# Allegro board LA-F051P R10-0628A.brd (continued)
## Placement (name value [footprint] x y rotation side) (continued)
SW3  -  [SW_NTC311-EA1T-A160T_4P]  3.52 23.28 270 top
T1  -  [TPC12]  124.99 68.06 0 top
T2  -  [TPC12]  124.74 70.44 0 top
T7  -  [TPC12]  122.93 54.05 0 top
T8  -  [TPC12]  126.72 53.25 0 top
T9  -  [TPC12]  109.06 73.38 0 top
T10  -  [TPC12]  121 75.69 180 bottom
T11  -  [TPC12]  119.99 74.51 180 bottom
T12  -  [TPC12]  112.38 41.98 180 bottom
T13  -  [TPC12]  111.4 44.71 180 bottom
T14  -  [TPC12]  144.87 55.56 0 top
T15  -  [TPC12]  146.03 56.6 0 top
T16  -  [TPC12]  111.18 45.98 180 bottom
T17  -  [TPC12]  112.24 43.61 180 bottom
T18  -  [TPC12]  144.79 51.65 0 top
T19  -  [TPC12]  124.56 47.71 180 bottom
T21  -  [TPC12]  127.56 55.28 0 top
T113  -  [TPC12]  110.49 41.96 180 bottom
T114  -  [TPC12]  110.67 43.61 180 bottom
T115  -  [TPC12]  145.83 52.82 0 top
T116  -  [TPC12]  143.05 54.03 0 top
T121  -  [TPC12]  152.68 46.08 180 bottom
T122  -  [TPC12]  133.91 66.53 0 top
T123  -  [TPC12]  133.71 57.06 0 top
T124  -  [TPC12]  154.16 59.03 180 bottom
T125  -  [TPC12]  149.58 57.94 0 top
T126  -  [TPC12]  157.61 49.82 180 bottom
T127  -  [TPC12]  155.27 49.84 180 bottom
T128  -  [TPC12]  154.33 53.15 180 bottom
T129  -  [TPC12]  153.81 54.78 180 bottom
T130  -  [TPC12]  155.12 48.01 180 bottom
T183  -  [TPC12]  189.21 64.09 0 top
T184  -  [TPC12]  183.49 69.81 0 top
T185  -  [TPC12]  181.46 56.73 0 top
T187  -  [TPC12]  184 68.67 180 bottom
T189  -  [TPC12]  184.32 61.38 180 bottom
T192  -  [TPC12]  141.99 42.92 180 bottom
T193  -  [TPC12]  29.49 59.57 180 bottom
T194  -  [TPC12]  28.19 59.57 180 bottom
T195  -  [TPC12]  116.92 56.93 0 top
T196  -  [TPC12]  118.21 56.73 0 top
T197  -  [TPC12]  179.06 55.92 180 bottom
T198  -  [TPC12]  122.48 56.9 0 top
T199  -  [TPC12]  122.91 67.5 0 top
T200  -  [TPC12]  119.2 52.71 0 top
T201  -  [TPC12]  119.28 54.03 0 top
TC25  -  [TPC12]  22.53 67.52 0 top
TC29  -  [TPC12]  22.56 66.2 0 top
TC35  -  [TPC12]  27.89 67.45 180 bottom
TC36  -  [TPC12]  22.58 56.88 0 top
TC38  -  [TPC12]  22.53 58.19 0 top
TC39  -  [TPC12]  51.84 74.91 0 top
TC40  -  [TPC12]  50.7 75.62 0 top
TC41  -  [TPC12]  49.43 75.22 0 top
TC42  -  [TPC12]  48.08 75.75 0 top
TC43  -  [TPC12]  45.21 58.51 180 bottom
TC44  -  [TPC12]  25.5 60.18 180 bottom
TC45  -  [TPC12]  26.62 59.34 180 bottom
U15  -  [NPCT650JAAYX_QFN32_5X5]  183.33 46.69 0 top
U18  -  [W25Q256FVEIG_WSON8]  185.01 46.94 180 bottom
U48  -  [PCA9515BDGKR_VSSOP8]  202.33 25.22 0 top
U664  -  [TPS22966DPUR_SON14_2X3]  34.32 42.89 180 top
U683  -  [NL17SZ14DFT2G_SOT353-5]  186.92 39.33 90 bottom
U699  -  [MC74VHC1G32DFT2G_SC70-5]  25.5 53.81 180 top
U716  -  [TPS22966DPUR_SON14_2X3]  170.1 16.33 0 top
U717  -  [TPS22966DPUR_SON14_2X3]  180.88 33.5 180 top
U719  -  [TPS22966DPUR_SON14_2X3]  51.93 18.95 90 top
U720  -  [TPS22966DPUR_SON14_2X3]  35.73 41.48 0 top
U722  -  [TPS65982_BGA_96P]  26.01 64.47 270 top
U728  -  [G9091-330TO1U_TSOT-23-5]  64.97 80.16 270 top
U729  -  [MC74VHC1G09DFT2G_SC70-5]  204 79.29 270 bottom
UA2  -  [ALC3246-CG_MQFN48_6X6]  30.71 27.48 180 top
UC2  -  [74AUP1G07GW_TSSOP5]  104.63 46.2 270 bottom
UC7  -  [TC7SH08FU_SSOP5]  161.14 59.78 0 top
UC8  -  [TC7SH08FU_SSOP5]  204.05 58.03 180 top
UC9  -  [TC7SH08FU_SSOP5]  164.38 70.33 270 top
UC10  -  [TC7SH08FU_SSOP5]  191.3 59 90 bottom
UC11  -  [TC7SH08FU_SSOP5]  52.34 41.33 0 top
UC12  -  [74AHC1G09GW_TSSOP5]  143.38 77.71 90 bottom
UC13  -  [TC7SH08FU_SSOP5]  199.51 57.49 180 top
UCPU1  -  [SKL-U_BGA_1356P-T]  152.12 72.31 0 bottom
UD19  -  [H9CCNNN8JTMLAR-NTM_FBGA_178P]  99.62 23.5 90 top
UD20  -  [H9CCNNN8JTMLAR-NTM_FBGA_178P]  115.14 23.5 90 top
UD21  -  [H9CCNNN8JTMLAR-NTM_FBGA_178P]  133.2 23.5 90 top
UD22  -  [H9CCNNN8JTMLAR-NTM_FBGA_178P]  148.77 23.5 90 top
UE4  -  [MCP23017T-E-ML_QFN28_6X6]  30.96 15.58 90 bottom
UE5  -  [MEC5085-LZY_DQFN132_11X11]  188.06 59.52 90 top
US2  -  [G547I1P81U_MSOP8]  24.36 49.23 90 top
UT1  -  [AR-4C_BGA_337P-T]  37.74 55.69 270 top
UT5  -  [W25Q80DVZPIG_WSON8]  49.15 38.31 90 top
UT6  -  [W25Q64FVZPIG_WSON8_6X5]  20.42 40.44 0 top
UZ19  -  [TPS22961DNYR_WSON8]  166.17 65.78 90 top
UZ22  -  [TPS22961DNYR_WSON8]  164.81 46.84 90 top
UZ23  -  [TPS22961DNYR_WSON8]  49.07 48.65 90 top
UZ24  -  [SY6288C20AAC_SOT23-5]  201.91 40.98 90 top
UZ25  -  [TPS22961DNYR_WSON8]  157.2 74.38 90 top
UZ26  -  [TPS22961DNYR_WSON8]  57.12 75.73 0 top
YC1  -  [Y_X3G024000DC1H_4P]  155.56 72.63 270 top
YC2  -  [Y_9H03220008_2P]  152.88 44.28 180 top
YE1  -  [Y_Q13FC135000040_2P]  184.38 51.9 0 top
YT1  -  [Y_7V25000014_4P]  34.51 65.79 90 top

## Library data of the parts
C2-C7 C265 C352 C355 C375-C377 C397 C398 C401 C402 C612-C617 C621 C623 C713 C715 C720-C722 C963 C1060-C1069 C1102 C1145 C1158-C1164 C1166-C1169 C1199-C1201 C1203 C1204 C1208 C1211-C1218 C1220-C1223 C1225 C1226 C1229 C1254 C1256-C1258 C1264 C1273-C1275 C1278-C1280 C1289 C1292 C1293 C1297 C1298 C1301 C1302 C1304 C1309 C1321 C1322 C1324 C1325 C1341 C1346 C2973 C2983 C2984 CA3 CA4 CA7 CA23-CA25 CA27-CA35 CA40 CA42 CA53-CA56 CA68-CA72 CA78 CA80 CA87 CA97 CA100 CA103-CA106 CA111 CC4 CC5 CC8 CC10 CC21-CC29 CC32 CC33 CC174-CC179 CC194 CC195 CC199 CC202-CC206 CC209 CC211-CC214 CC217 CC218 CC220 CC223 CC224 CC240 CC248-CC253 CC264-CC270 CC282 CC283 CD1 CD3 CD5 CD7 CD29 CD33 CD37 CD39 CD41 CD43-CD47 CD51 CD53 CD57 CD59 CD61 CD63 CD85 CD87 CD89 CD91 CD117-CD120 CD129 CD132 CD133 CD135 CD136 CD139 CD140 CD142-CD146 CD148-CD181 CD183-CD187 CE3 CE10 CE13 CE14 CE17 CE21 CE22 CE38-CE41 CE43 CE46-CE68 CE72 CH11-CH14 CH95 CS44 CT43 CT44 CT53-CT56 CT95-CT98 CT144 CT151 CT152 CZ78 CZ82-CZ87 CZ89-CZ92 MC3 PC100-PC102 PC104-PC107 PC203-PC205 PC210-PC218 PC301 PC310 PC311 PC318 PC330-PC332 PC334-PC336 PC400-PC403 PC405 PC406 PC500 PC501 PC511 PC513 PC514 PC525 PC602-PC607 PC609 PC614 PC617 PC618 PC700-PC702 PC704 PC707 PC712 PC713 PC800 PC801 PC803 PC804 PC806 PC807 PC900 PC901 PC903 PC904 PC906 PC907 PC1004 PC1006 PC1014 PC1019-PC1022 PC1056 PC1064 PC1065 PC1067-PC1072 PC1074-PC1081 PC1083-PC1085 PC1087-PC1092 PC1094-PC1099 PC1103 PC1104 PC1106 PC1110-PC1113 PC1116-PC1118 PC1123 PC1124 PC1126-PC1128 PC1131-PC1134 PC1400 PC1408-PC1412 PC1417-PC1420 PC1535 PC1536 PC1538 = C_0402
C8 C94 C712 C716 C719 C962 C1143 C1205 C1339 C1347-C1350 C1353 C1985 C2982 CA74 CA82 CA83 CA86 CA107-CA110 CC31 CC34 CC35 CC279 CC280 CD2 CD4 CD6 CD8 CD30 CD34 CD38 CD42 CD58 CD60 CD62 CD64 CD86 CD88 CD90 CD92 CD147 CD182 CD196 CD197 CE4 CE42 CE45 CT9 CT88-CT90 CT164 CT165 PC103 PC200-PC202 PC206-PC209 PC247 PC309 PC312 PC314-PC317 PC319-PC329 PC333 PC337 PC404 PC407 PC502-PC510 PC512 PC515-PC524 PC526 PC527 PC600 PC601 PC608 PC610-PC613 PC615 PC616 PC703 PC1005 PC1007 PC1082 PC1086 PC1100-PC1102 PC1105 PC1107 PC1108 PC1114 PC1115 PC1119-PC1121 PC1125 PC1129 PC1130 PC1200-PC1246 PC1250-PC1252 PC1256-PC1258 PC1310-PC1321 PC1330-PC1334 PC1336 PC1337 PC1344-PC1354 PC1401-PC1406 PC1413-PC1416 = C_0603
C95-C98 C135 C618 C1345 C1354 C1984 CC95 CC125 CC181 CC182 CC185 CC186 CC225 CC256-CC261 CC281 CE70 CE71 CR24-CR26 CT1-CT8 CT17-CT26 CT29-CT42 CT47 CT50 CT52 CT57 CT62-CT68 CT71 CT72 CT74 CT80 CT81 CT83-CT86 CT91-CT94 CT99-CT103 CT107 CT108 CT149 CT150 CT153-CT163 CT166-CT179 PC1259-PC1305 PC1322-PC1328 PC1338-PC1343 = C_0201
C303 PC1306-PC1309 PC1329 = C_B2
CA2 CA5 CA6 CA98 CA99 CA101 CA102 CA112 CC210 CC271-CC274 PC108 PC302-PC307 PC313 PC528 PC529 PC705 PC706 PC708-PC711 PC802 PC805 PC902 PC905 PC1066 PC1093 PC1109 PC1122 = C_0805
CMOS1 JTAG1 RH442 RH443 = SHORTPADS: User Part Number: PART#
D72 D73 D94 = BAT54CW-7-F_SOT323-3
D75-D80 D82-D91 = ESD101-B1-02ELS_TSSLP-2-4-2
D81 DE11 DZ1-DZ3 = RB751S40T1G_SOD523-2
D122 PD102 = AZ5125-01HPR7G_SOD523-2
D123 = BZT52C15LP-7_DFN1006-2-2
DA1 DA2 = AZ5125-02SPR7G_SOT23-3
DA3 DA4 = PJDLC05C_SOT23-3
DA5 DA7 = ESD207-B1-02EL_TSLP-2-19-2
DI1 = IP4292CZ10-TBR_XSON10_2P5X1
DI2-DI4 = AZC199-02SPR7G_SOT23-3
DI7 = PESD24VS2UT_SOT23-3
FD1-FD4 = FIDUCIAL_C40M80
H1 H4 H7 H9 H12 H13 H18 H19 = H_2P0
H3 = H_1P8N
H6 H10 H11 H14-H17 = H_3P3
H20-H22 H24 H25 = EMIST_SUL-12A2M_1P
H23 = H_2P3X1P8N
H26 = H_3P2X0P8
JAPS1 = ACES_50506-01841-P01_18P
JBATT1 = FOX_GS73091-10272-7H_9P-T
JCAM JTS = CVILU_CI1806M2HRP-NH_6P
JDEG1 JLPDE1 = HB_A531015-SCHR21_10P
JEDP = ACES_50398-04041-001_40P
JFAN1 JSPK1 = ACES_50224-00401-001_4P
JHP1 = SINGA_2SJ3095-022111F_6P-T
JIO1 = JXT_FP270H-061G1AM_61P
JKB1 = E-T_6710K-Y15M-31L_15P
JNGFF1 = CONCR_213AAAA32FA_67P
JNGFF2 = CONCR_213MAAA32FA_67P-T
JP100 = ACES_88266-05001_5P
JPA1-JPA3 PJP14 PJP15 PJP300 PJP601 PJP800 PJP900 = JUMP_43X39
JRTC1 = ACES_50278-00201-001_2P
JSPI1 = ACES_50696-0200M-P01_20P
JTP1 = ACES_50506-00841-P01_8P
JUART = ACES_50207-00471-P01_4P-T
JUSB2 = TE_C-PT13-067_9P-T
JUSBC1 = JAE_DX07SA24XJ2_24P-T
JXDP1 = SAMTE_BSH-030-01-L-D-A_60P
L2-L5 = MURAT_BLM15PX181SN1D_2P
L55 ML9-ML11 = INPAQ_MCM1012B900F06BP_4P
LA2 LA4 = MURAT_BLM15PX600SN1D_2P
LA3 = MURAT_BLM21PG600SN1D_L0805_2P
LA6 LA7 = CHILI_PBY100505T-600Y-N_2P
LA14 = MURAT_BLM15BB220SN1D_2P
LED10-LED14 = LED_27-11-T1D-CP1Q1RY-3C_2P
LT1 = COILC_XFL4012-601MEC_2P
LT14 = CHILI_PBY160808T-300Y-N_2P
LT106 PL100 PL101 PL103 PL104 PL300 PL500 PL600 PL700 PL1004 = TAI-T_HCB2012KF-121T50_2P
MD9 MD10 = PESD5V0U2BT_SOT23-3
ML6 ML7 = MURAT_DLW21HN900SQ2L_4P
ML12 ML13 = MURAT_DLW21SN670HQ2L_4P
PC1073 PC1135 PC1537 = C_D
PD100 PD101 = TVNST52302AB0_SOT523-3
PD200 = BAT54CW_SOT323-3
PD201-PD206 PD300-PD302 = SDMK0340L-7-F_SOD323-2
PH1005-PH1009 PR100-PR106 PR201-PR230 PR232-PR235 PR237 PR239-PR275 PR277-PR291 PR301 PR305 PR307 PR310 PR312 PR316 PR317 PR320 PR322 PR323 PR325 PR327 PR400-PR413 PR502 PR504 PR506 PR508 PR509 PR511 PR600 PR601 PR603-PR605 PR608 PR610 PR611 PR700 PR701 PR704 PR705 PR707 PR708 PR800 PR802 PR804 PR805 PR901 PR902 PR904 PR905 PR1028 PR1058 PR1060-PR1065 PR1067-PR1075 PR1077-PR1079 PR1081 PR1084 PR1085 PR1087-PR1090 PR1092-PR1099 PR1107 PR1109 PR1112 PR1115 PR1118 PR1120-PR1124 PR1126-PR1128 PR1402 PR1404-PR1408 PR1412-PR1415 PR1417 PR1418 PR1422-PR1425 R7 R78-R81 R220 R249 R252 R287 R288 R290-R292 R535 R536 R540 R545 R884 R886 R910-R913 R916 R1006 R1027 R1103-R1105 R1140 R1141 R1161 R1162 R1175 R1176 R1178 R1179 R1186-R1188 R1191 R1216 R1255 R1299 R1376 R1377 R1443 R1446 R1454 R1460 R1462 R1468 R1472-R1478 R1873 R2662 RA15-RA20 RA24 RA25 RA27 RA28 RA35 RA37-RA39 RA41 RA48-RA51 RA57 RA58 RA60-RA62 RA75-RA77 RC1-RC7 RC9-RC18 RC20-RC23 RC25-RC27 RC29 RC44-RC50 RC52-RC67 RC69 RC71-RC75 RC77-RC96 RC109 RC110 RC112-RC115 RC120-RC124 RC126 RC128-RC141 RC152 RC153 RC157 RC158 RC161 RC163 RC165-RC168 RC175-RC178 RC183-RC191 RC215 RC217-RC220 RC224-RC227 RC229 RC230 RC236 RC237 RC239-RC243 RC245 RC246 RC272 RC277 RC280 RC283-RC285 RC288 RC291-RC293 RC312 RC313 RC319 RD17 RD19 RD21 RD22 RD25 RD26 RD35-RD38 RD45-RD48 RD51-RD118 RE2 RE3 RE6 RE7 RE13 RE14 RE22-RE27 RE31 RE33-RE36 RE52-RE61 RE63-RE86 RE89-RE103 RE121 RH24 RH56 RH58 RH59 RH127 RH129 RH139 RH144-RH153 RH438 RH440 RH441 RH456 RH461 RH556 RH557 RH562 RH563 RN19 RN20 RT1 RT2 RT5 RT10 RT46 RT113 RT190 RT199-RT201 RT242 RTCR1 RTCR2 RZ75 = R_0402
PJP500 PJP501 PJP600 PJP1002 = JUMP_43X118
PJP700 PJP1400 PJP1401 = JUMP_43X79
PL102 = MURAT_BLM15AG102SN1D_2P
PL301 = L_7X7X3_M_2P
PL501 = TAI-T_TMPC0518HP-1R5MG-D_2P
PL504 = CYNTE_PCMC063T-1R5MN_2P
PL601 = CYNTE_PCMB051B-1R0MS_2P
PL701 = L_5X5X3_M_2P
PL800 PL900 PL1400 PL1402 = TAI-T_HCB1608KF-121T3_L0603_2P
PL801 PL901 = TOKO_1239AS-H-2R2N-P2_2P
PL1005 = MAG_MMD05CZR47M_4P
PL1100-PL1102 = L_7X7X3_M
PL1401 PL1403 = TOKO_1277AS-H-1R0N-P2_2P
PQ100 = FDV301N_NL_SOT23-3
PQ101 QE9 = MMST3904-7-F_SOT323-3
PQ200-PQ203 PQ210-PQ212 = AON2405_DFN6-8
PQ204 PQ205 PQ213 PQ214 PQ221 PQ222 = NTR4502PT1G_SOT23-3
PQ206-PQ209 PQ215-PQ219 PQ223 PQ400 QA1 QA3 QC2 QE12-QE14 QH7-QH9 = DMN66D0LDW-7_SOT363-6
PQ220 PQ224 QA6 QA9 = SSM3K7002FU_SC70-3
PQ302 = L2N7002WT1G_SC70-3
PQ303 = SIR472DP-T1-GE3_POWERPAK8-5
PQ304 = SI7716ADN-T1-GE3_POWERPAK8-5
PQ305 = SI4483ADY-T1-GE3_SO8
PQ1302 = AON7934_DFN3X3A8-10
PR107 PR903 R2672 = R_0805
PR108 PR303 PR304 PR309 PR311 PR314 PR315 PR318 PR319 PR326 PR503 PR510 PR606 PR607 PR609 PR709 PR801 PR806 PR900 PR906 PR1024 PR1025 PR1027 PR1029 PR1059 PR1066 PR1076 PR1080 PR1083 PR1103 PR1110 PR1119 PR1125 PR1400 PR1401 PR1409 PR1411 PR1419-PR1421 R104 R250 R251 R289 R1200 R1210 R1212 R1436-R1442 R1444 R1445 R2663-R2665 RA26 RA30 RA31 RA54 RA59 RA63-RA65 RC19 RC154 RC155 RC169 RC171 RC213 RC221 RC228 RC247 RC248 RC290 RC296-RC298 RC301 RC310 RE32 RE62 RE104 RE105 RE107 RE120 RZ76 = R0402_0OHM
PR200 PR300 PR313 = R_1206_4P-D
PR306 PR321 PR501 PR507 PR1086 PR1101 PR1106 PR1114 = R_1206
PR308 PR324 PR500 PR505 PR602 PR612 PR702 PR703 PR803 PR1082 PR1091 PR1100 PR1102 PR1105 PR1111 PR1113 PR1116 PR1403 PR1416 R531 RA81 RA82 RC97 RT114 RT241 = R_0603
PR512 PR513 R1322 R1326 R1329 R1342 R1344 R1393 R2669 = R0805_0OHM
PRP100 RP5 RP6 RPE5 RPE7 = RP_0804_8P4R
PU200 = INA199A1DCKR_SC70-6
PU201 PU203 PU400 = LM393DMR2G_MICRO8
PU202 = RT9069-33GB_SOT23-5
PU300 = BQ24777ARUYR_WQFN28_4X4
PU401 PU402 = M74VHC1GT00DFT2G_SC70-5
PU500 = SY8286BRAC_QFN20_3X3
PU501 = SY8288CRAC_QFN20_3X3
PU600 = SY8210AQVC_QFN19_4X3
PU700 = SY8286RAC_QFN20_3X3
PU800 PU900 = TLV62150RGTR_QFN16_3X3
PU1000 = ISL95859AHRTZ-T_TQFN40_5X5
PU1100-PU1102 = AOZ5049QI_QFN24_5X3P5-S
PU1305 = ISL95808HRZ-TS2378_DFN8_2X2
PU1400 = TPS62134ARGT_QFN16_3X3
PU1401 = TPS62134BRGT_QFN16_3X3
Q40 Q41 Q71 QT19 = L2N7002WT1G_SC-70-3
Q70 = SI3457BDV-T1-E3_TSOP6
Q72 QZ9 = DMG2301U-7_SOT23-3
QE3 QE4 QE8 QE10 QE11 = MMBT3904WT1G_SC70-3
R9 R10 R60 R1403 R1405 R1457-R1459 R1461 R1463-R1465 R1471 RC51 RC316 RC317 RE87 RE88 RH126 RT3 RT4 RT6-RT9 RT11 RT12 RT15-RT18 RT21-RT23 RT25 RT26 RT33-RT40 RT43-RT45 RT47-RT52 RT119-RT121 RT164 RT187 RT188 RT243 = R_0201
R1125 R1318 R1320 R1323 R1325 R1327 R1333 R1335 R1343 R2670 R2671 RA80 RC143 RC170 RC211 RC214 RC216 RC299 RC304 RC309 RH357 = R0603_0OHM
RC172 RC318 = MURAT_BLM18EG221SN1D_2P
SW1 = SW_SSAL120100_3P
SW2 = SW_SKRBAAE010_4P
SW3 = SW_NTC311-EA1T-A160T_4P
T1 T2 T7-T19 T21 T113-T116 T121-T130 T183-T185 T187 T189 T192-T201 TC25 TC29 TC35 TC36 TC38-TC45 = TPC12
U15 = NPCT650JAAYX_QFN32_5X5
U18 = W25Q256FVEIG_WSON8
U48 = PCA9515BDGKR_VSSOP8
U664 U716 U717 U719 U720 = TPS22966DPUR_SON14_2X3
U683 = NL17SZ14DFT2G_SOT353-5
U699 = MC74VHC1G32DFT2G_SC70-5
U722 = TPS65982_BGA_96P
U728 = G9091-330TO1U_TSOT-23-5
U729 = MC74VHC1G09DFT2G_SC70-5
UA2 = ALC3246-CG_MQFN48_6X6
UC2 = 74AUP1G07GW_TSSOP5
UC7-UC11 UC13 = TC7SH08FU_SSOP5
UC12 = 74AHC1G09GW_TSSOP5
UCPU1 = SKL-U_BGA_1356P-T
UD19-UD22 = H9CCNNN8JTMLAR-NTM_FBGA_178P
UE4 = MCP23017T-E-ML_QFN28_6X6
UE5 = MEC5085-LZY_DQFN132_11X11
US2 = G547I1P81U_MSOP8
UT1 = AR-4C_BGA_337P-T
UT5 = W25Q80DVZPIG_WSON8
UT6 = W25Q64FVZPIG_WSON8_6X5
UZ19 UZ22 UZ23 UZ25 UZ26 = TPS22961DNYR_WSON8
UZ24 = SY6288C20AAC_SOT23-5
YC1 = Y_X3G024000DC1H_4P
YC2 = Y_9H03220008_2P
YE1 = Y_Q13FC135000040_2P
YT1 = Y_7V25000014_4P

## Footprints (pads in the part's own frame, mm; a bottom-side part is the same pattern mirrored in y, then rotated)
74AHC1G09GW_TSSOP5
  oval 0.381x1.346 smd: 1(0,0) 2(0.65,0) 3(1.3,0) 4(1.3,1.79) 5(0,1.79)
74AUP1G07GW_TSSOP5
  oval 0.381x1.346 smd: 1(0,0) 2(0.65,0) 3(1.3,0) 4(1.3,1.79) 5(0,1.79)
ACES_50207-00471-P01_4P-T
  oval 0.508x0.991 smd: 1(0,0) 2(-0.8,0) 3(-1.6,0) 4(-2.4,0)
  rect 1.194x1.702 smd: 5(-3.7,1.45) 6(1.3,1.45)
ACES_50224-00401-001_4P
  oval 0.61x1.549 smd: 1(0,0) 2(1,0) 3(2,0) 4(3,0)
  rect 1.194x1.803 smd: 5(4.3,-3.875) 6(-1.3,-3.875)
ACES_50278-00201-001_2P
  oval 0.787x1.905 smd: 1(0,0) 2(1.25,0)
  rect 1.295x3.353 smd: 3(-2.85,-4.925) 4(4.1,-4.925)
ACES_50398-04041-001_40P
  oval 0.254x1.295 smd: 1(0,0) 2(0.5,0) 3(1,0) 4(1.5,0) 5(2,0) 6(2.5,0) 7(3,0) 8(3.5,0) 9(4,0) 10(4.5,0) 11(5,0) 12(5.5,0) 13(6,0) 14(6.5,0) 15(7,0) 16(7.5,0) 17(8,0) 18(8.5,0) 19(9,0) 20(9.5,0) 21(10,0) 22(10.5,0) 23(11,0) 24(11.5,0) 25(12,0) 26(12.5,0) 27(13,0) 28(13.5,0) 29(14,0) 30(14.5,0) 31(15,0) 32(15.5,0) 33(16,0) 34(16.5,0) 35(17,0) 36(17.5,0) 37(18,0) 38(18.5,0) 39(19,0) 40(19.5,0)
  rect 1.194x3.2 smd: 41(-2.4,1.95) 45(21.9,1.95)
  rect 2.311x1.295 smd: 42(0.85,3.9) 43(9.75,3.9) 44(18.65,3.9)
ACES_50506-00841-P01_8P
  oval 0.305x0.889 smd: 1(0,0) 2(0.5,0) 3(1,0) 4(1.5,0) 5(2,0) 6(2.5,0) 7(3,0) 8(3.5,0)
  rect 0.991x2.007 smd: 9(-2.1,-3.05) 10(5.6,-3.05)
ACES_50506-01841-P01_18P
  oval 0.305x0.889 smd: 1(0,0) 2(0.5,0) 3(1,0) 4(1.5,0) 5(2,0) 6(2.5,0) 7(3,0) 8(3.5,0) 9(4,0) 10(4.5,0) 11(5,0) 12(5.5,0) 13(6,0) 14(6.5,0) 15(7,0) 16(7.5,0) 17(8,0) 18(8.5,0)
  rect 0.991x2.007 smd: 19(-2.1,-3.05) 20(10.6,-3.05)
ACES_50696-0200M-P01_20P
  oval 0.305x0.787 smd: 1(0,0) 2(-0.5,0) 3(-1,0) 4(-1.5,0) 5(-2,0) 6(-2.5,0) 7(-3,0) 8(-3.5,0) 9(-4,0) 10(-4.5,0) 11(-5,0) 12(-5.5,0) 13(-6,0) 14(-6.5,0) 15(-7,0) 16(-7.5,0) 17(-8,0) 18(-8.5,0) 19(-9,0) 20(-9.5,0)
  rect 0.406x0.787 smd: 21(1,-2.5) 22(-10.5,-2.5)
ACES_88266-05001_5P
  oval 0.787x2.007 smd: 1(0,0) 2(1.25,0) 3(2.5,0) 4(3.75,0) 5(5,0)
  rect 2.007x2.489 smd: 6(7.2,-4.05) 7(-2.2,-4.05)
ALC3246-CG_MQFN48_6X6
  oval 0.889x0.203 smd: 1(0,0) 2(0,-0.4) 3(0,-0.8) 4(0,-1.2) 5(0,-1.6) 6(0,-2) 7(0,-2.4) 8(0,-2.8) 9(0,-3.2) 10(0,-3.6) 11(0,-4) 12(0,-4.4) 25(6.1,-4.4) 26(6.1,-4) 27(6.1,-3.6) 28(6.1,-3.2) 29(6.1,-2.8) 30(6.1,-2.4) 31(6.1,-2) 32(6.1,-1.6) 33(6.1,-1.2) 34(6.1,-0.8) 35(6.1,-0.4) 36(6.1,0)
  oval 0.203x0.889 smd: 13(0.85,-5.25) 14(1.25,-5.25) 15(1.65,-5.25) 16(2.05,-5.25) 17(2.45,-5.25) 18(2.85,-5.25) 19(3.25,-5.25) 20(3.65,-5.25) 21(4.05,-5.25) 22(4.45,-5.25) 23(4.85,-5.25) 24(5.25,-5.25) 37(5.25,0.85) 38(4.85,0.85) 39(4.45,0.85) 40(4.05,0.85) 41(3.65,0.85) 42(3.25,0.85) 43(2.85,0.85) 44(2.45,0.85) 45(2.05,0.85) 46(1.65,0.85) 47(1.25,0.85) 48(0.85,0.85)
  rect 4.394x4.394 smd: 49(3.05,-2.2)
AON2405_DFN6-8
  oval 0.305x0.33 smd: 1(0,0) 2(0.65,0) 3(1.3,0) 4(1.3,1.725) 5(0.65,1.725) 6(0,1.725)
  rect 0.94x0.991 smd: 7(0.325,0.863)
  rect 0.229x0.813 smd: 8(1.315,0.902)
AON7934_DFN3X3A8-10
  oval 0.457x0.508 smd: 1(0,0) 2(0.65,0) 3(1.3,0) 4(1.95,0) 5(1.95,2.76) 6(1.3,2.76) 7(0.65,2.76) 8(0,2.76)
  rect 2.54x1.041 smd: 9(0.975,1.813)
  rect 2.54x0.559 smd: 10(0.975,0.708)
AOZ5049QI_QFN24_5X3P5-S
  oval 0.254x0.762 smd: 1(0,0) 2(0.5,0) 3(1,0) 4(1.5,0) 5(2,0)
  rect 3.15x1.473 smd: 6(1.47,1.31)
  custom 0.588x0.588 smd: 7(1,2.425)
  rect 1.956x0.864 smd: 8(1.25,4.787)
  oval 0.762x0.254 smd: 9(-0.675,2.925) 10(-0.675,2.425) 11(-0.675,1.925) 12(-0.675,1.425) 13(-0.675,0.925) 14(-0.675,0.425)
AR-4C_BGA_337P-T
  round 0.254 smd: A1(0,0) A23(-10.12,0) AA2(-0.46,9.2) AA22(-9.66,9.2) AB2(-0.46,9.66) AB3(-0.92,9.66) AB4(-1.38,9.66) AB5(-1.84,9.66) AB6(-2.3,9.66) AB7(-2.76,9.66) AB8(-3.22,9.66) AB9(-3.68,9.66) AB10(-4.14,9.66) AB11(-4.6,9.66) AB12(-5.06,9.66) AB13(-5.52,9.66) AB14(-5.98,9.66) AB15(-6.44,9.66) AB16(-6.9,9.66) AB17(-7.36,9.66) AB18(-7.82,9.66) AB19(-8.28,9.66) AB20(-8.74,9.66) AB21(-9.2,9.66) AB22(-9.66,9.66) AC1(0,10.12) AC23(-10.12,10.12) B2(-0.46,0.46) B3(-0.92,0.46) B4(-1.38,0.46) B5(-1.84,0.46) B6(-2.3,0.46) B7(-2.76,0.46) B8(-3.22,0.46) B9(-3.68,0.46) B10(-4.14,0.46) B11(-4.6,0.46) B12(-5.06,0.46) B13(-5.52,0.46) B14(-5.98,0.46) B15(-6.44,0.46) B16(-6.9,0.46) B17(-7.36,0.46) B18(-7.82,0.46) B19(-8.28,0.46) B20(-8.74,0.46) B21(-9.2,0.46) B22(-9.66,0.46) C2(-0.46,0.92) C22(-9.66,0.92) D2(-0.46,1.38) D4(-1.16,1.16) D5(-1.81,1.16) D6(-2.46,1.16) D8(-3.11,1.16) D9(-3.76,1.16) D11(-4.41,1.16) D12(-5.06,1.16) D13(-5.71,1.16) D15(-6.36,1.16) D16(-7.01,1.16) D18(-7.66,1.16) D19(-8.31,1.16) D20(-8.96,1.16) D22(-9.66,1.38) E2(-0.46,1.84) E4(-1.16,1.81) E5(-1.81,1.81) E6(-2.46,1.81) E8(-3.11,1.81) E9(-3.76,1.81) E11(-4.41,1.81) E12(-5.06,1.81) E13(-5.71,1.81) E15(-6.36,1.81) E16(-7.01,1.81) E18(-7.66,1.81) E19(-8.31,1.81) E20(-8.96,1.81) E22(-9.66,1.84) F2(-0.46,2.3) F4(-1.16,2.46) F5(-1.81,2.46) F6(-2.46,2.46) F8(-3.11,2.46) F9(-3.76,2.46) F11(-4.41,2.46) F12(-5.06,2.46) F13(-5.71,2.46) F15(-6.36,2.46) F16(-7.01,2.46) F18(-7.66,2.46) F19(-8.31,2.46) F20(-8.96,2.46) F22(-9.66,2.3) G2(-0.46,2.76) G22(-9.66,2.76) H2(-0.46,3.22) H4(-1.16,3.11) H5(-1.81,3.11) H6(-2.46,3.11) H8(-3.11,3.11) H9(-3.76,3.11) H11(-4.41,3.11) H12(-5.06,3.11) H13(-5.71,3.11) H15(-6.36,3.11) H16(-7.01,3.11) H18(-7.66,3.11) H19(-8.31,3.11) H20(-8.96,3.11) H22(-9.66,3.22) J2(-0.46,3.68) J4(-1.16,3.76) J5(-1.81,3.76) J6(-2.46,3.76) J8(-3.11,3.76) J9(-3.76,3.76) J11(-4.41,3.76) J12(-5.06,3.76) J13(-5.71,3.76) J15(-6.36,3.76) J16(-7.01,3.76) J18(-7.66,3.76) J19(-8.31,3.76) J20(-8.96,3.76) J22(-9.66,3.68) K2(-0.46,4.14) K22(-9.66,4.14) L2(-0.46,4.6) L4(-1.16,4.41) L5(-1.81,4.41) L6(-2.46,4.41) L8(-3.11,4.41) L9(-3.76,4.41) L11(-4.41,4.41) L12(-5.06,4.41) L13(-5.71,4.41) L15(-6.36,4.41) L16(-7.01,4.41) L18(-7.66,4.41) L19(-8.31,4.41) L20(-8.96,4.41) L22(-9.66,4.6) M2(-0.46,5.06) M4(-1.16,5.06) M5(-1.81,5.06) M6(-2.46,5.06) M8(-3.11,5.06) M9(-3.76,5.06) M11(-4.41,5.06) M12(-5.06,5.06) M13(-5.71,5.06) M15(-6.36,5.06) M16(-7.01,5.06) M18(-7.66,5.06) M19(-8.31,5.06) M20(-8.96,5.06) M22(-9.66,5.06) N2(-0.46,5.52) N4(-1.16,5.71) N5(-1.81,5.71) N6(-2.46,5.71) N8(-3.11,5.71) N9(-3.76,5.71) N11(-4.41,5.71) N12(-5.06,5.71) N13(-5.71,5.71) N15(-6.36,5.71) N16(-7.01,5.71) N18(-7.66,5.71) N19(-8.31,5.71) N20(-8.96,5.71) N22(-9.66,5.52) P2(-0.46,5.98) P22(-9.66,5.98) R2(-0.46,6.44) R4(-1.16,6.36) R5(-1.81,6.36) R6(-2.46,6.36) R8(-3.11,6.36) R9(-3.76,6.36) R11(-4.41,6.36) R12(-5.06,6.36) R13(-5.71,6.36) R15(-6.36,6.36) R16(-7.01,6.36) R18(-7.66,6.36) R19(-8.31,6.36) R20(-8.96,6.36) R22(-9.66,6.44) T2(-0.46,6.9) T4(-1.16,7.01) T5(-1.81,7.01) T6(-2.46,7.01) T8(-3.11,7.01) T9(-3.76,7.01) T11(-4.41,7.01) T12(-5.06,7.01) T13(-5.71,7.01) T15(-6.36,7.01) T16(-7.01,7.01) T18(-7.66,7.01) T19(-8.31,7.01) T20(-8.96,7.01) T22(-9.66,6.9) U2(-0.46,7.36) U22(-9.66,7.36) V2(-0.46,7.82) V4(-1.16,7.66) V5(-1.81,7.66) V6(-2.46,7.66) V8(-3.11,7.66) V9(-3.76,7.66) V11(-4.41,7.66) V12(-5.06,7.66) V13(-5.71,7.66) V15(-6.36,7.66) V16(-7.01,7.66) V18(-7.66,7.66) V19(-8.31,7.66) V20(-8.96,7.66) V22(-9.66,7.82) W2(-0.46,8.28) W4(-1.16,8.31) W5(-1.81,8.31) W6(-2.46,8.31) W8(-3.11,8.31) W9(-3.76,8.31) W11(-4.41,8.31) W12(-5.06,8.31) W13(-5.71,8.31) W15(-6.36,8.31) W16(-7.01,8.31) W18(-7.66,8.31) W19(-8.31,8.31) W20(-8.96,8.31) W22(-9.66,8.28) Y2(-0.46,8.74) Y4(-1.16,8.96) Y5(-1.81,8.96) Y6(-2.46,8.96) Y8(-3.11,8.96) Y9(-3.76,8.96) Y11(-4.41,8.96) Y12(-5.06,8.96) Y13(-5.71,8.96) Y15(-6.36,8.96) Y16(-7.01,8.96) Y18(-7.66,8.96) Y19(-8.31,8.96) Y20(-8.96,8.96) Y22(-9.66,8.74)
  oval 0.178x0.33 smd: A2(-0.46,0) A3(-0.92,0) A4(-1.38,0) A5(-1.84,0) A6(-2.3,0) A7(-2.76,0) A8(-3.22,0) A9(-3.68,0) A10(-4.14,0) A11(-4.6,0) A12(-5.06,0) A13(-5.52,0) A14(-5.98,0) A15(-6.44,0) A16(-6.9,0) A17(-7.36,0) A18(-7.82,0) A19(-8.28,0) A20(-8.74,0) A21(-9.2,0) A22(-9.66,0) AC2(-0.46,10.12) AC3(-0.92,10.12) AC4(-1.38,10.12) AC5(-1.84,10.12) AC6(-2.3,10.12) AC7(-2.76,10.12) AC8(-3.22,10.12) AC9(-3.68,10.12) AC10(-4.14,10.12) AC11(-4.6,10.12) AC12(-5.06,10.12) AC13(-5.52,10.12) AC14(-5.98,10.12) AC15(-6.44,10.12) AC16(-6.9,10.12) AC17(-7.36,10.12) AC18(-7.82,10.12) AC19(-8.28,10.12) AC20(-8.74,10.12) AC21(-9.2,10.12) AC22(-9.66,10.12)
  oval 0.33x0.178 smd: AA1(0,9.2) AA23(-10.12,9.2) AB1(0,9.66) AB23(-10.12,9.66) B1(0,0.46) B23(-10.12,0.46) C1(0,0.92) C23(-10.12,0.92) D1(0,1.38) D23(-10.12,1.38) E1(0,1.84) E23(-10.12,1.84) F1(0,2.3) F23(-10.12,2.3) G1(0,2.76) G23(-10.12,2.76) H1(0,3.22) H23(-10.12,3.22) J1(0,3.68) J23(-10.12,3.68) K1(0,4.14) K23(-10.12,4.14) L1(0,4.6) L23(-10.12,4.6) M1(0,5.06) M23(-10.12,5.06) N1(0,5.52) N23(-10.12,5.52) P1(0,5.98) P23(-10.12,5.98) R1(0,6.44) R23(-10.12,6.44) T1(0,6.9) T23(-10.12,6.9) U1(0,7.36) U23(-10.12,7.36) V1(0,7.82) V23(-10.12,7.82) W1(0,8.28) W23(-10.12,8.28) Y1(0,8.74) Y23(-10.12,8.74)
AZ5125-01HPR7G_SOD523-2
  rect 0.61x0.787 smd: 1(0,0) 2(1.5,0)
AZ5125-02SPR7G_SOT23-3
  oval 1.016x1.524 smd: 1(0,0) 2(0.965,2.083) 3(-0.965,2.083)
AZC199-02SPR7G_SOT23-3
  oval 1.016x1.524 smd: 1(0,0) 2(0.965,2.083) 3(-0.965,2.083)
BAT54CW-7-F_SOT323-3
  oval 0.711x0.889 smd: 1(0,0) 2(-0.65,-1.9) 3(0.65,-1.9)
BAT54CW_SOT323-3
  oval 0.711x0.889 smd: 1(0,0) 2(-0.65,-1.9) 3(0.65,-1.9)
BQ24777ARUYR_WQFN28_4X4
  oval 0.889x0.203 smd: 1(0,0) 2(0,-0.4) 3(0,-0.8) 4(0,-1.2) 5(0,-1.6) 6(0,-2) 7(0,-2.4) 15(4.1,-2.4) 16(4.1,-2) 17(4.1,-1.6) 18(4.1,-1.2) 19(4.1,-0.8) 20(4.1,-0.4) 21(4.1,0)
  oval 0.203x0.889 smd: 8(0.85,-3.25) 9(1.25,-3.25) 10(1.65,-3.25) 11(2.05,-3.25) 12(2.45,-3.25) 13(2.85,-3.25) 14(3.25,-3.25) 22(3.25,0.85) 23(2.85,0.85) 24(2.45,0.85) 25(2.05,0.85) 26(1.65,0.85) 27(1.25,0.85) 28(0.85,0.85)
  rect 2.591x2.591 smd: 29(2.05,-1.2)
BZT52C15LP-7_DFN1006-2-2
  rect 0.406x0.711 smd: 1(0,0) 2(0.7,0)
C_0201
  rect 0.381x0.356 smd: 1(0,0) 2(0.584,0)
C_0402
  rect 0.508x0.559 smd: 1(0,0) 2(0.914,0)
C_0603
  rect 0.635x0.889 smd: 1(0,0) 2(1.397,0)
C_0805
  rect 0.813x1.397 smd: 1(0,0) 2(1.702,0)
C_B2
  rect 1.346x2.692 smd: 1(0,0) 2(-2.75,0)
C_D
  rect 2.388x2.896 smd: 1(0,0) 2(6.1,0)
CHILI_PBY100505T-600Y-N_2P
  rect 0.457x0.508 smd: 1(0,0) 2(0.85,0)
CHILI_PBY160808T-300Y-N_2P
  rect 0.559x1.041 smd: 1(0,0) 2(1.3,0)
COILC_XFL4012-601MEC_2P
  rect 0.991x3.404 smd: 1(0,0) 2(2.37,0)
CONCR_213AAAA32FA_67P
  round 1.092 hole 1.092 unplated: (-0.75,-5.275)
  round 1.6 hole 1.6 unplated: (19.25,-5.275)
  oval 0.305x1.549 smd: 1(0,0) 2(0.25,-7.55) 3(0.5,0) 4(0.75,-7.55) 5(1,0) 6(1.25,-7.55) 7(1.5,0) 8(3.75,-7.55) 9(4,0) 10(4.25,-7.55) 11(4.5,0) 12(4.75,-7.55) 13(5,0) 14(5.25,-7.55) 15(5.5,0) 16(5.75,-7.55) 17(6,0) 18(6.25,-7.55) 19(6.5,0) 20(6.75,-7.55) 21(7,0) 22(7.25,-7.55) 23(7.5,0) 24(7.75,-7.55) 25(8,0) 26(8.25,-7.55) 27(8.5,0) 28(8.75,-7.55) 29(9,0) 30(9.25,-7.55) 31(9.5,0) 32(9.75,-7.55) 33(10,0) 34(10.25,-7.55) 35(10.5,0) 36(10.75,-7.55) 37(11,0) 38(11.25,-7.55) 39(11.5,0) 40(11.75,-7.55) 41(12,0) 42(12.25,-7.55) 43(12.5,0) 44(12.75,-7.55) 45(13,0) 46(13.25,-7.55) 47(13.5,0) 48(13.75,-7.55) 49(14,0) 50(14.25,-7.55) 51(14.5,0) 52(14.75,-7.55) 53(15,0) 54(15.25,-7.55) 55(15.5,0) 56(15.75,-7.55) 57(16,0) 58(16.25,-7.55) 59(16.5,0) 60(16.75,-7.55) 61(17,0) 62(17.25,-7.55) 63(17.5,0) 64(17.75,-7.55) 65(18,0) 66(18.25,-7.55) 67(18.5,0)
  rect 1.194x2.743 smd: 68(-1.1,-0.775) 69(19.6,-0.775)
CONCR_213MAAA32FA_67P-T
  round 1.092 hole 1.092 unplated: (-0.75,-5.275)
  round 1.6 hole 1.6 unplated: (19.25,-5.275)
  oval 0.305x1.549 smd: 1(0,0) 2(0.25,-7.55) 3(0.5,0) 4(0.75,-7.55) 5(1,0) 6(1.25,-7.55) 7(1.5,0) 8(1.75,-7.55) 9(2,0) 10(2.25,-7.55) 11(2.5,0) 12(2.75,-7.55) 13(3,0) 14(3.25,-7.55) 15(3.5,0) 16(3.75,-7.55) 17(4,0) 18(4.25,-7.55) 19(4.5,0) 20(4.75,-7.55) 21(5,0) 22(5.25,-7.55) 23(5.5,0) 24(5.75,-7.55) 25(6,0) 26(6.25,-7.55) 27(6.5,0) 28(6.75,-7.55) 29(7,0) 30(7.25,-7.55) 31(7.5,0) 32(7.75,-7.55) 33(8,0) 34(8.25,-7.55) 35(8.5,0) 36(8.75,-7.55) 37(9,0) 38(9.25,-7.55) 39(9.5,0) 40(9.75,-7.55) 41(10,0) 42(10.25,-7.55) 43(10.5,0) 44(10.75,-7.55) 45(11,0) 46(11.25,-7.55) 47(11.5,0) 48(11.75,-7.55) 49(12,0) 50(12.25,-7.55) 51(12.5,0) 52(12.75,-7.55) 53(13,0) 54(13.25,-7.55) 55(13.5,0) 56(13.75,-7.55) 57(14,0) 58(14.25,-7.55) 59(16.5,0) 60(16.75,-7.55) 61(17,0) 62(17.25,-7.55) 63(17.5,0) 64(17.75,-7.55) 65(18,0) 66(18.25,-7.55) 67(18.5,0)
  rect 1.194x2.743 smd: 68(-1.1,-0.775) 69(19.6,-0.775)
CVILU_CI1806M2HRP-NH_6P
  oval 0.508x0.991 smd: 1(0,0) 2(0.8,0) 3(1.6,0) 4(2.4,0) 5(3.2,0) 6(4,0)
  rect 1.194x1.702 smd: 7(5.3,-1.95) 8(-1.3,-1.95)
CYNTE_PCMB051B-1R0MS_2P
  rect 2.159x2.794 smd: 1(0,0) 2(4.35,0)
CYNTE_PCMC063T-1R5MN_2P
  rect 2.159x3.505 smd: 1(0,0) 2(5.85,0)
DMG2301U-7_SOT23-3
  oval 1.016x1.524 smd: 1(0,0) 2(0.965,2.083) 3(-0.965,2.083)
DMN66D0LDW-7_SOT363-6
  oval 0.432x0.61 smd: 1(0,0) 2(0.65,0) 3(1.3,0) 4(1.3,1.9) 5(0.65,1.9) 6(0,1.9)
E-T_6710K-Y15M-31L_15P
  oval 0.305x0.965 smd: 1(0,0) 2(0.5,0) 3(1,0) 4(1.5,0) 5(2,0) 6(2.5,0) 7(3,0) 8(3.5,0) 9(4,0) 10(4.5,0) 11(5,0) 12(5.5,0) 13(6,0) 14(6.5,0) 15(7,0)
  rect 0.305x1.143 smd: 16(7.885,-2.965) 17(-0.885,-2.965)
EMIST_SUL-12A2M_1P
  rect 6.909x1.194 smd: 1(0,0)
ESD101-B1-02ELS_TSSLP-2-4-2
  rect 0.279x0.381 smd: 1(0,0) 2(0.38,0)
ESD207-B1-02EL_TSLP-2-19-2
  rect 0.356x0.61 smd: 1(0,0) 2(0.65,0)
FDV301N_NL_SOT23-3
  oval 1.016x1.524 smd: 1(0,0) 2(0.965,2.083) 3(-0.965,2.083)
FIDUCIAL_C40M80
  round 1.016 smd: 1(0,0)
FOX_GS73091-10272-7H_9P-T
  rect 0.66x5.004 smd: 1(0,0) 2(-1.5,0) 3(-3,0) 4(-4.5,0) 5(-6,0) 6(-7.5,0) 7(-9,0) 8(-10.5,0) 9(-12,0)
  rect 2.489x2.997 smd: 10(-14.5,4.45) 11(2.5,4.45)
G547I1P81U_MSOP8
  oval 0.381x1.549 smd: 1(0,0) 2(0.65,0) 3(1.3,0) 4(1.95,0) 5(1.95,4.37) 6(1.3,4.37) 7(0.65,4.37) 8(0,4.37)
G9091-330TO1U_TSOT-23-5
  oval 0.508x0.965 smd: 1(0,0) 2(0.95,0) 3(1.9,0) 4(1.9,2.35) 5(0,2.35)
H9CCNNN8JTMLAR-NTM_FBGA_178P
  round 0.343 smd: A1(0,0) A2(0.8,0) A3(1.6,0) A4(2.4,0) A5(3.2,0) A6(4,0) A8(5.601,0) A9(6.401,0) A10(7.201,0) A11(8.001,0) A12(8.801,0) A13(9.601,0) B1(0,-0.65) B2(0.8,-0.65) B3(1.6,-0.65) B4(2.4,-0.65) B5(3.2,-0.65) B6(4,-0.65) B8(5.601,-0.65) B9(6.401,-0.65) B10(7.201,-0.65) B11(8.001,-0.65) B12(8.801,-0.65) B13(9.601,-0.65) C2(0.8,-1.3) C3(1.6,-1.3) C4(2.4,-1.3) C5(3.2,-1.3) C6(4,-1.3) C8(5.601,-1.3) C9(6.401,-1.3) C10(7.201,-1.3) C11(8.001,-1.3) C12(8.801,-1.3) D2(0.8,-1.95) D3(1.6,-1.95) D4(2.4,-1.95) D5(3.2,-1.95) D6(4,-1.95) D8(5.601,-1.95) D9(6.401,-1.95) D10(7.201,-1.95) D11(8.001,-1.95) D12(8.801,-1.95) E2(0.8,-2.6) E3(1.6,-2.6) E4(2.4,-2.6) E5(3.2,-2.6) E6(4,-2.6) E8(5.601,-2.6) E9(6.401,-2.6) E10(7.201,-2.6) E11(8.001,-2.6) E12(8.801,-2.6) F2(0.8,-3.25) F3(1.6,-3.25) F4(2.4,-3.25) F5(3.2,-3.25) F6(4,-3.25) F8(5.601,-3.25) F9(6.401,-3.25) F10(7.201,-3.25) F11(8.001,-3.25) F12(8.801,-3.25) G2(0.8,-3.9) G3(1.6,-3.9) G4(2.4,-3.9) G5(3.2,-3.9) G6(4,-3.9) G8(5.601,-3.9) G9(6.401,-3.9) G10(7.201,-3.9) G11(8.001,-3.9) G12(8.801,-3.9) H2(0.8,-4.55) H3(1.6,-4.55) H4(2.4,-4.55) H5(3.2,-4.55) H6(4,-4.55) H8(5.601,-4.55) H9(6.401,-4.55) H10(7.201,-4.55) H11(8.001,-4.55) H12(8.801,-4.55) J2(0.8,-5.2) J3(1.6,-5.2) J4(2.4,-5.2) J5(3.2,-5.2) J6(4,-5.2) J8(5.601,-5.2) J9(6.401,-5.2) J10(7.201,-5.2) J11(8.001,-5.2) J12(8.801,-5.2) K2(0.8,-5.85) K3(1.6,-5.85) K4(2.4,-5.85) K5(3.2,-5.85) K6(4,-5.85) K8(5.601,-5.85) K9(6.401,-5.85) K10(7.201,-5.85) K11(8.001,-5.85) K12(8.801,-5.85) L2(0.8,-6.5) L3(1.6,-6.5) L4(2.4,-6.5) L5(3.2,-6.5) L6(4,-6.5) L8(5.601,-6.5) L9(6.401,-6.5) L10(7.201,-6.5) L11(8.001,-6.5) L12(8.801,-6.5) M2(0.8,-7.15) M3(1.6,-7.15) M4(2.4,-7.15) M5(3.2,-7.15) M6(4,-7.15) M8(5.601,-7.15) M9(6.401,-7.15) M10(7.201,-7.15) M11(8.001,-7.15) M12(8.801,-7.15) N2(0.8,-7.8) N3(1.6,-7.8) N4(2.4,-7.8) N5(3.2,-7.8) N6(4,-7.8) N8(5.601,-7.8) N9(6.401,-7.8) N10(7.201,-7.8) N11(8.001,-7.8) N12(8.801,-7.8) P2(0.8,-8.45) P3(1.6,-8.45) P4(2.4,-8.45) P5(3.2,-8.45) P6(4,-8.45) P8(5.601,-8.45) P9(6.401,-8.45) P10(7.201,-8.45) P11(8.001,-8.45) P12(8.801,-8.45) R2(0.8,-9.1) R3(1.6,-9.1) R4(2.4,-9.1) R5(3.2,-9.1) R6(4,-9.1) R8(5.601,-9.1) R9(6.401,-9.1) R10(7.201,-9.1) R11(8.001,-9.1) R12(8.801,-9.1) T1(0,-9.75) T2(0.8,-9.75) T3(1.6,-9.75) T4(2.4,-9.75) T5(3.2,-9.75) T6(4,-9.75) T8(5.601,-9.75) T9(6.401,-9.75) T10(7.201,-9.75) T11(8.001,-9.75) T12(8.801,-9.75) T13(9.601,-9.75) U1(0,-10.4) U2(0.8,-10.4) U3(1.6,-10.4) U4(2.4,-10.4) U5(3.2,-10.4) U6(4,-10.4) U8(5.601,-10.4) U9(6.401,-10.4) U10(7.201,-10.4) U11(8.001,-10.4) U12(8.801,-10.4) U13(9.601,-10.4)
H_1P8N
  round 1.803 hole 1.803 unplated: (0,0)
H_2P0
  round 2.515 hole 2.007: 1(0,0)
H_2P3X1P8N
  oval 2.311x1.803 hole 2.311x1.803 unplated: (0,0)
H_3P2X0P8
  oval 3.708x1.295 hole 3.2x0.787: 1(0,0)
H_3P3
  round 3.81 hole 3.302: 1(0,0)
HB_A531015-SCHR21_10P
  oval 0.305x0.889 smd: 1(0,0) 2(0.5,0) 3(1,0) 4(1.5,0) 5(2,0) 6(2.5,0) 7(3,0) 8(3.5,0) 9(4,0) 10(4.5,0)
  rect 0.991x2.007 smd: 11(6.6,-3.05) 12(-2.1,-3.05)
INA199A1DCKR_SC70-6
  oval 0.406x0.889 smd: 1(0,0) 2(0.65,0) 3(1.3,0) 4(1.3,2.2) 5(0.65,2.2) 6(0,2.2)
INPAQ_MCM1012B900F06BP_4P
  rect 0.711x0.305 smd: 1(0,0) 2(1.25,0) 3(1.25,-0.5) 4(0,-0.5)
IP4292CZ10-TBR_XSON10_2P5X1
  oval 0.254x0.889 smd: 1(0,0)
  oval 0.254x0.838 smd: 2(0.5,-0.025) 3(1,-0.025) 4(1.5,-0.025) 5(2,-0.025) 6(2,1.125) 7(1.5,1.125) 8(1,1.125) 9(0.5,1.125) 10(0,1.125)
ISL95808HRZ-TS2378_DFN8_2X2
  oval 0.254x0.787 smd: 1(0,0) 2(0.5,0) 3(1,0) 4(1.5,0) 5(1.5,2.2) 6(1,2.2) 7(0.5,2.2) 8(0,2.2)
  rect 1.549x0.889 smd: 9(0.75,1.1)
ISL95859AHRTZ-T_TQFN40_5X5
  oval 0.889x0.203 smd: 1(0,0) 2(0,-0.4) 3(0,-0.8) 4(0,-1.2) 5(0,-1.6) 6(0,-2) 7(0,-2.4) 8(0,-2.8) 9(0,-3.2) 10(0,-3.6) 21(5.1,-3.6) 22(5.1,-3.2) 23(5.1,-2.8) 24(5.1,-2.4) 25(5.1,-2) 26(5.1,-1.6) 27(5.1,-1.2) 28(5.1,-0.8) 29(5.1,-0.4) 30(5.1,0)
  oval 0.203x0.889 smd: 11(0.75,-4.35) 12(1.15,-4.35) 13(1.55,-4.35) 14(1.95,-4.35) 15(2.35,-4.35) 16(2.75,-4.35) 17(3.15,-4.35) 18(3.55,-4.35) 19(3.95,-4.35) 20(4.35,-4.35) 31(4.35,0.75) 32(3.95,0.75) 33(3.55,0.75) 34(3.15,0.75) 35(2.75,0.75) 36(2.35,0.75) 37(1.95,0.75) 38(1.55,0.75) 39(1.15,0.75) 40(0.75,0.75)
  rect 3.505x3.505 smd: 41(2.55,-1.8)
JAE_DX07SA24XJ2_24P-T
  round 0.762 hole 0.762 unplated: (-0.85,-0.66)
  oval 0.94x0.762 hole 0.94x0.762 unplated: (6.35,-0.66)
  custom 0.275x0.275 hole 0.61x1.6: 1(-1.85,-5.06) 4(7.35,-5.06)
  oval 1.092x2.108 hole 0.61x1.6: 2(-1.85,-2.06) 3(7.35,-2.06)
  rect 1.499x1.6 smd: 7(0.75,-5.91) 8(4.75,-5.91)
  oval 0.305x1.092 smd: A1(0,0) A2(0.5,0) A3(1,0) A4(1.5,0) A5(2,0) A6(2.5,0) A7(3,0) A8(3.5,0) A9(4,0) A10(4.5,0) A11(5,0) A12(5.5,0)
  round 0.61 hole 0.406: B1(5.55,-1.31) B2(5.15,-2.01) B3(4.35,-2.01) B4(3.95,-1.31) B5(3.55,-2.01) B6(3.15,-1.31) B7(2.35,-1.31) B8(1.95,-2.01) B9(1.55,-1.31) B10(1.15,-2.01) B11(0.35,-2.01) B12(-0.05,-1.31)
JUMP_43X39
  custom 0.191x0.191 smd: 1(0,0) 2(0.914,0)
JUMP_43X79
  custom 0.188x0.188 smd: 1(0,0) 2(1.1,0)
JUMP_43X118
  custom 0.187x0.187 smd: 1(0,0) 2(1.1,0)
JXT_FP270H-061G1AM_61P
  oval 0.305x0.787 smd: 1(0,0) 3(0.6,0) 5(1.2,0) 7(1.8,0) 9(2.4,0) 11(3,0) 13(3.6,0) 15(4.2,0) 17(4.8,0) 19(5.4,0) 21(6,0) 23(6.6,0) 25(7.2,0) 27(7.8,0) 29(8.4,0) 31(9,0) 33(9.6,0) 35(10.2,0) 37(10.8,0) 39(11.4,0) 41(12,0) 43(12.6,0) 45(13.2,0) 47(13.8,0) 49(14.4,0) 51(15,0) 53(15.6,0) 55(16.2,0) 57(16.8,0) 59(17.4,0) 61(18,0)
  oval 0.305x0.66 smd: 2(0.3,2.875) 4(0.9,2.875) 6(1.5,2.875) 8(2.1,2.875) 10(2.7,2.875) 12(3.3,2.875) 14(3.9,2.875) 16(4.5,2.875) 18(5.1,2.875) 20(5.7,2.875) 22(6.3,2.875) 24(6.9,2.875) 26(7.5,2.875) 28(8.1,2.875) 30(8.7,2.875) 32(9.3,2.875) 34(9.9,2.875) 36(10.5,2.875) 38(11.1,2.875) 40(11.7,2.875) 42(12.3,2.875) 44(12.9,2.875) 46(13.5,2.875) 48(14.1,2.875) 50(14.7,2.875) 52(15.3,2.875) 54(15.9,2.875) 56(16.5,2.875) 58(17.1,2.875) 60(17.7,2.875)
  rect 0.305x1.143 smd: 62(-0.65,0.375) 63(18.65,0.375)
L2N7002WT1G_SC70-3
  oval 0.711x0.889 smd: 1(0,0) 2(0.65,1.9) 3(-0.65,1.9)
L2N7002WT1G_SC-70-3
  oval 0.711x0.889 smd: 1(0,0) 2(-0.65,-1.9) 3(0.65,-1.9)
L_5X5X3_M_2P
  rect 2.159x2.794 smd: 1(0,0) 2(4.35,0)
L_7X7X3_M
  custom 0.591x0.591 smd: 1(0,0) 4(6.05,0)
  rect 0.762x0.508 smd: 2(0.8,0) 3(5.25,0)
L_7X7X3_M_2P
  rect 2.362x3.505 smd: 1(0,0) 2(6.05,0)
LED_27-11-T1D-CP1Q1RY-3C_2P
  rect 0.991x0.991 smd: 1(0,0) 2(1.9,0)
LM393DMR2G_MICRO8
  oval 0.381x1.041 smd: 1(0,0) 2(0.65,0) 3(1.3,0) 4(1.95,0) 5(1.95,4.24) 6(1.3,4.24) 7(0.65,4.24) 8(0,4.24)
M74VHC1GT00DFT2G_SC70-5
  oval 0.406x0.508 smd: 1(0,0) 2(0.65,0) 3(1.3,0) 4(1.3,1.9) 5(0,1.9)
MAG_MMD05CZR47M_4P
  custom 0.54x0.54 smd: 1(0,0) 4(4.35,0)
  rect 0.762x0.508 smd: 2(0.699,0) 3(3.652,0)
MC74VHC1G09DFT2G_SC70-5
  oval 0.406x0.508 smd: 1(0,0) 2(0.65,0) 3(1.3,0) 4(1.3,1.9) 5(0,1.9)
MC74VHC1G32DFT2G_SC70-5
  oval 0.457x0.711 smd: 1(-0.65,-0.925) 2(0,-0.925) 3(0.65,-0.925) 4(0.65,0.925) 5(-0.65,0.925)
MCP23017T-E-ML_QFN28_6X6
  oval 0.457x1.041 smd: 1(0,0) 2(0.65,0) 3(1.3,0) 4(1.95,0) 5(2.6,0) 6(3.25,0) 7(3.9,0) 15(3.9,5.95) 16(3.25,5.95) 17(2.6,5.95) 18(1.95,5.95) 19(1.3,5.95) 20(0.65,5.95) 21(0,5.95)
  oval 1.041x0.457 smd: 8(4.925,1.025) 9(4.925,1.675) 10(4.925,2.325) 11(4.925,2.975) 12(4.925,3.625) 13(4.925,4.275) 14(4.925,4.925) 22(-1.025,4.925) 23(-1.025,4.275) 24(-1.025,3.625) 25(-1.025,2.975) 26(-1.025,2.325) 27(-1.025,1.675) 28(-1.025,1.025)
  rect 3.708x3.708 smd: 29(1.95,2.975)
MEC5085-LZY_DQFN132_11X11
  oval 0.279x0.711 smd: A1(0,0) A2(0.5,0) A3(1,0) A4(1.5,0) A5(2,0) A6(2.5,0) A7(3,0) A8(3.5,0) A9(4,0) A10(4.5,0) A11(5,0) A12(5.5,0) A13(6,0) A14(6.5,0) A15(7,0) A16(7.5,0) A33(7.5,10.9) A34(7,10.9) A35(6.5,10.9) A36(6,10.9) A37(5.5,10.9) A38(5,10.9) A39(4.5,10.9) A40(4,10.9) A41(3.5,10.9) A42(3,10.9) A43(2.5,10.9) A44(2,10.9) A45(1.5,10.9) A46(1,10.9) A47(0.5,10.9) A48(0,10.9)
  oval 0.711x0.279 smd: A17(9.2,1.7) A18(9.2,2.2) A19(9.2,2.7) A20(9.2,3.2) A21(9.2,3.7) A22(9.2,4.2) A23(9.2,4.7) A24(9.2,5.2) A25(9.2,5.7) A26(9.2,6.2) A27(9.2,6.7) A28(9.2,7.2) A29(9.2,7.7) A30(9.2,8.2) A31(9.2,8.7) A32(9.2,9.2) A49(-1.7,9.2) A50(-1.7,8.7) A51(-1.7,8.2) A52(-1.7,7.7) A53(-1.7,7.2) A54(-1.7,6.7) A55(-1.7,6.2) A56(-1.7,5.7) A57(-1.7,5.2) A58(-1.7,4.7) A59(-1.7,4.2) A60(-1.7,3.7) A61(-1.7,3.2) A62(-1.7,2.7) A63(-1.7,2.2) A64(-1.7,1.7)
  oval 0.305x0.61 smd: B1(-0.25,0.85) B2(0.25,0.85) B3(0.75,0.85) B4(1.25,0.85) B5(1.75,0.85) B6(2.25,0.85) B7(2.75,0.85) B8(3.25,0.85) B9(3.75,0.85) B10(4.25,0.85) B11(4.75,0.85) B12(5.25,0.85) B13(5.75,0.85) B14(6.25,0.85) B15(6.75,0.85) B16(7.25,0.85) B17(7.75,0.85) B35(7.75,10.05) B36(7.25,10.05) B37(6.75,10.05) B38(6.25,10.05) B39(5.75,10.05) B40(5.25,10.05) B41(4.75,10.05) B42(4.25,10.05) B43(3.75,10.05) B44(3.25,10.05) B45(2.75,10.05) B46(2.25,10.05) B47(1.75,10.05) B48(1.25,10.05) B49(0.75,10.05) B50(0.25,10.05) B51(-0.25,10.05)
  oval 0.61x0.305 smd: B18(8.35,1.45) B19(8.35,1.95) B20(8.35,2.45) B21(8.35,2.95) B22(8.35,3.45) B23(8.35,3.95) B24(8.35,4.45) B25(8.35,4.95) B26(8.35,5.45) B27(8.35,5.95) B28(8.35,6.45) B29(8.35,6.95) B30(8.35,7.45) B31(8.35,7.95) B32(8.35,8.45) B33(8.35,8.95) B34(8.35,9.45) B52(-0.85,9.45) B53(-0.85,8.95) B54(-0.85,8.45) B55(-0.85,7.95) B56(-0.85,7.45) B57(-0.85,6.95) B58(-0.85,6.45) B59(-0.85,5.95) B60(-0.85,5.45) B61(-0.85,4.95) B62(-0.85,4.45) B63(-0.85,3.95) B64(-0.85,3.45) B65(-0.85,2.95) B66(-0.85,2.45) B67(-0.85,1.95) B68(-0.85,1.45)
  rect 5.004x5.004 smd: C1(3.75,5.45)
MMBT3904WT1G_SC70-3
  oval 0.711x0.889 smd: 1(0,0) 2(0.65,1.9) 3(-0.65,1.9)
MMST3904-7-F_SOT323-3
  oval 0.711x0.889 smd: 1(0,0) 2(0.65,1.9) 3(-0.65,1.9)
MURAT_BLM15AG102SN1D_2P
  rect 0.457x0.508 smd: 1(0,0) 2(0.85,0)
MURAT_BLM15BB220SN1D_2P
  rect 0.508x0.762 smd: 1(0,0) 2(0.75,0)
MURAT_BLM15PX181SN1D_2P
  rect 0.508x0.762 smd: 1(0,0) 2(0.75,0)
MURAT_BLM15PX600SN1D_2P
  rect 0.457x0.508 smd: 1(0,0) 2(0.85,0)
MURAT_BLM18EG221SN1D_2P
  rect 0.66x1.041 smd: 1(0,0) 2(1.2,0)
MURAT_BLM21PG600SN1D_L0805_2P
  rect 0.991x1.753 smd: 1(0,0) 2(1.5,0)
MURAT_DLW21HN900SQ2L_4P
  rect 0.889x0.356 smd: 1(0,0) 2(1.7,0) 3(1.7,0.85) 4(0,0.85)
MURAT_DLW21SN670HQ2L_4P
  rect 0.889x0.406 smd: 1(0,0) 2(1.7,0) 3(1.7,0.8) 4(0,0.8)
NL17SZ14DFT2G_SOT353-5
  oval 0.381x1.219 smd: 1(0,0) 2(0.65,0) 3(1.3,0) 4(1.3,1.9) 5(0,1.9)
NPCT650JAAYX_QFN32_5X5
  oval 0.889x0.254 smd: 1(0,0) 2(0,-0.5) 3(0,-1) 4(0,-1.5) 5(0,-2) 6(0,-2.5) 7(0,-3) 8(0,-3.5) 17(5.1,-3.5) 18(5.1,-3) 19(5.1,-2.5) 20(5.1,-2) 21(5.1,-1.5) 22(5.1,-1) 23(5.1,-0.5) 24(5.1,0)
  oval 0.254x0.889 smd: 9(0.8,-4.3) 10(1.3,-4.3) 11(1.8,-4.3) 12(2.3,-4.3) 13(2.8,-4.3) 14(3.3,-4.3) 15(3.8,-4.3) 16(4.3,-4.3) 25(4.3,0.8) 26(3.8,0.8) 27(3.3,0.8) 28(2.8,0.8) 29(2.3,0.8) 30(1.8,0.8) 31(1.3,0.8) 32(0.8,0.8)
  rect 3.505x3.505 smd: 33(2.55,-1.75)
NTR4502PT1G_SOT23-3
  oval 1.016x1.524 smd: 1(0,0) 2(0.965,2.083) 3(-0.965,2.083)
PCA9515BDGKR_VSSOP8
  oval 0.381x1.575 smd: 1(0,0) 2(0.65,0) 3(1.3,0) 4(1.95,0) 5(1.95,4.35) 6(1.3,4.35) 7(0.65,4.35) 8(0,4.35)
PESD5V0U2BT_SOT23-3
  oval 1.016x1.524 smd: 1(0,0) 2(0.965,2.083) 3(-0.965,2.083)
PESD24VS2UT_SOT23-3
  oval 1.016x1.524 smd: 1(0,0) 2(0.965,2.083) 3(-0.965,2.083)
PJDLC05C_SOT23-3
  oval 1.016x1.524 smd: 1(0,0) 2(0.965,2.083) 3(-0.965,2.083)
R0402_0OHM
  rect 0.508x0.559 smd: 1(0,0) 2(0.914,0)
R0603_0OHM
  rect 0.635x0.889 smd: 1(0,0) 2(1.397,0)
R0805_0OHM
  rect 0.813x1.397 smd: 1(0,0) 2(1.702,0)
R_0201
  rect 0.381x0.356 smd: 1(0,0) 2(0.584,0)
R_0402
  rect 0.508x0.559 smd: 1(0,0) 2(0.914,0)
R_0603
  rect 0.635x0.889 smd: 1(0,0) 2(1.397,0)
R_0805
  rect 0.813x1.397 smd: 1(0,0) 2(1.702,0)
R_1206
  rect 1.016x1.651 smd: 1(0,0) 2(2.667,0)
R_1206_4P-D
  custom 0.371x0.371 smd: 1(0,0) 4(3.327,0)
  custom 0.114x0.114 smd: 2(0.775,0) 3(2.553,0)
RB751S40T1G_SOD523-2
  rect 0.406x0.406 smd: 1(0,0) 2(1.4,0)
RP_0804_8P4R
  oval 0.66x0.254 smd: 1(0,0) 2(0,-0.5) 3(0,-1) 4(0,-1.5) 5(1.15,-1.5) 6(1.15,-1) 7(1.15,-0.5) 8(1.15,0)
RT9069-33GB_SOT23-5
  oval 0.711x0.991 smd: 1(0,0) 2(0.95,0) 3(1.9,0) 4(1.9,2.6) 5(0,2.6)
SAMTE_BSH-030-01-L-D-A_60P
  round 1.016 hole 1.016 unplated: (-2.81,5.53) (17.316,5.53)
  oval 0.279x2.261 smd: 1(0,0) 2(0,5.728) 3(0.5,0) 4(0.5,5.728) 5(1,0) 6(1,5.728) 7(1.5,0) 8(1.5,5.728) 9(2,0) 10(2,5.728) 11(2.5,0) 12(2.5,5.728) 13(3,0) 14(3,5.728) 15(3.5,0) 16(3.5,5.728) 17(4,0) 18(4,5.728) 19(4.5,0) 20(4.5,5.728) 21(5,0) 22(5,5.728) 23(5.5,0) 24(5.5,5.728) 25(6,0) 26(6,5.728) 27(6.5,0) 28(6.5,5.728) 29(7,0) 30(7,5.728) 31(7.5,0) 32(7.5,5.728) 33(8,0) 34(8,5.728) 35(8.5,0) 36(8.5,5.728) 37(9,0) 38(9,5.728) 39(9.5,0) 40(9.5,5.728) 41(10,0) 42(10,5.728) 43(10.5,0) 44(10.5,5.728) 45(11,0) 46(11,5.728) 47(11.5,0) 48(11.5,5.728) 49(12,0) 50(12,5.728) 51(12.5,0) 52(12.5,5.728) 53(13,0) 54(13,5.728) 55(13.5,0) 56(13.5,5.728) 57(14,0) 58(14,5.728) 59(14.5,0) 60(14.5,5.728)
SDMK0340L-7-F_SOD323-2
  rect 1.346x0.66 smd: 1(0,0) 2(2.4,0)
SHORTPADS
  custom 0.19x0.19 smd: 1(-0.483,0) 2(0.483,0)
SI3457BDV-T1-E3_TSOP6
  oval 0.508x1.448 smd: 1(0,0) 2(1,0) 3(2,0) 4(2,2.425) 5(1,2.425) 6(0,2.425)
SI4483ADY-T1-GE3_SO8
  oval 0.635x1.727 smd: 1(0,0) 2(1.27,0) 3(2.54,0) 4(3.81,0) 5(3.81,5.285) 6(2.54,5.285) 7(1.27,5.285) 8(0,5.285)
SI7716ADN-T1-GE3_POWERPAK8-5
  oval 0.406x0.991 smd: 1(0,0) 2(0.66,0) 3(1.32,0) 4(1.98,0)
  custom 0.559x0.559 smd: 5(0.99,2.247)
SINGA_2SJ3095-022111F_6P-T
  oval 0.991x1.803 hole 0.61x1.397: 1(0,0) 2(-9.5,5.5) 3(0,5.2) 4(0,7.8) 5(-9.5,0) 6(-9.5,2.75) 7(0,2.65)
SIR472DP-T1-GE3_POWERPAK8-5
  oval 0.61x1.27 smd: 1(0,0) 2(1.27,0) 3(2.54,0) 4(3.81,0)
  custom 1.105x1.105 smd: 5(1.905,3.715)
SKL-U_BGA_1356P-T
  round 0.356 smd: A3(-0.965,0) A70(-40.166,0) B2(-0.483,0.483) B71(-40.629,0.462) BA1(0,22.166) BA71(-40.629,22.166) BB2(-0.462,22.628) BB70(-40.166,22.628) C1(0,0.965)
  round 0.33 smd: A4(-1.615,0) A69(-39.516,0) AY1(0,21.516) AY71(-40.629,21.516) B3(-1.118,0.635) B70(-39.999,0.63) BA2(-0.629,21.999) BA70(-39.999,21.999) BB3(-1.113,22.628) BB69(-39.516,22.628) C2(-0.635,1.118) C71(-40.629,1.113) D1(0,1.615)
  round 0.305 smd: A5(-2.266,0) A68(-38.866,0) AA2(-0.975,10.804) AA4(-1.951,10.804) AA63(-35.427,10.719) AA64(-36.077,10.719) AA65(-36.727,10.719) AA66(-37.377,10.719) AA67(-38.028,10.719) AA68(-38.678,10.719) AA69(-39.328,10.719) AA70(-39.978,10.719) AA71(-40.629,10.719) AB4(-1.951,11.467) AB6(-2.729,11.181) AB7(-3.379,11.181) AB8(-4.029,11.181) AB9(-4.679,11.181) AB10(-5.33,11.181) AB11(-5.98,11.181) AB12(-6.63,11.181) AB13(-7.28,11.181) AB15(-8.126,11.305) AB16(-8.776,11.305) AB17(-9.426,11.305) AB18(-10.077,11.305) AB19(-10.727,11.305) AB20(-11.377,11.305) AB21(-12.027,11.305) AB62(-34.958,11.176) AC3(-1.626,12.13) AC63(-35.427,11.633) AC64(-36.077,11.633) AC65(-36.727,11.633) AC66(-37.377,11.633) AC67(-38.028,11.633) AC68(-38.678,11.633) AC69(-39.328,11.633) AC70(-39.978,11.633) AC71(-40.629,11.633) AD4(-1.951,12.792) AD6(-2.729,12.248) AD7(-3.379,12.248) AD8(-4.029,12.248) AD9(-4.679,12.248) AD10(-5.33,12.248) AD11(-5.98,12.248) AD12(-6.63,12.248) AD13(-7.28,12.248) AD15(-8.126,12.143) AD16(-8.776,12.143) AD17(-9.426,12.143) AD18(-10.077,12.143) AD19(-10.727,12.143) AD20(-11.377,12.143) AD21(-12.027,12.143) AD62(-34.958,12.09) AE62(-34.958,13.005) AE63(-35.427,12.547) AE64(-36.077,12.547) AE65(-36.727,12.547) AE66(-37.377,12.547) AE67(-38.028,12.547) AE68(-38.678,12.547) AE69(-39.328,12.547) AF2(-0.975,13.455) AF4(-1.951,13.455) AF6(-2.729,13.315) AF7(-3.379,13.315) AF8(-4.029,13.315) AF9(-4.679,13.315) AF10(-5.33,13.315) AF11(-5.98,13.315) AF12(-6.63,13.315) AF13(-7.28,13.315) AF15(-8.126,12.982) AF16(-8.776,12.982) AF17(-9.426,12.982) AF18(-10.077,12.982) AF19(-10.727,12.982) AF20(-11.377,12.982) AF21(-12.027,12.982) AF63(-35.427,13.462) AF64(-36.077,13.462) AF65(-36.727,13.462) AF66(-37.377,13.462) AF67(-38.028,13.462) AF68(-38.678,13.253) AF69(-39.328,13.253) AG4(-1.951,14.118) AG15(-8.126,13.82) AG16(-8.776,13.82) AG17(-9.426,13.82) AG18(-10.077,13.82) AG19(-10.727,13.82) AG20(-11.377,13.82) AG21(-12.027,13.82) AG62(-34.958,13.919) AG69(-39.003,13.916) AH3(-1.626,14.781) AH6(-2.729,14.381) AH7(-3.379,14.381) AH8(-4.029,14.381) AH9(-4.679,14.381) AH10(-5.33,14.381) AH11(-5.98,14.381) AH12(-6.63,14.381) AH13(-7.28,14.381) AH63(-35.427,14.376) AH64(-36.077,14.376) AH65(-36.727,14.376) AH66(-37.377,14.376) AH67(-38.028,14.376) AJ4(-1.951,15.444) AJ15(-8.126,14.658) AJ16(-8.776,14.658) AJ17(-9.426,14.658) AJ18(-10.077,14.658) AJ19(-10.727,14.658) AJ20(-11.377,14.658) AJ21(-12.027,14.658) AJ62(-34.958,14.833) AK6(-2.729,15.321) AK7(-3.379,15.321) AK8(-4.029,15.321) AK9(-4.679,15.321) AK10(-5.33,15.321) AK11(-5.98,15.321) AK12(-6.63,15.321) AK13(-7.28,15.321) AK15(-8.126,15.496) AK16(-8.776,15.496) AK17(-9.426,15.496) AK18(-10.077,15.496) AK19(-10.727,15.496) AK20(-11.377,15.496) AK21(-12.027,15.496) AK22(-12.719,15.323) AK23(-13.633,15.323) AK25(-14.547,15.323) AK27(-15.462,15.323) AK28(-16.376,15.323) AK30(-17.291,15.323) AK32(-18.205,15.323) AK33(-19.119,15.323) AK35(-20.034,15.323) AK37(-20.948,15.323) AK38(-21.863,15.323) AK40(-22.777,15.323) AK42(-23.691,15.323) AK43(-24.606,15.323) AK45(-25.52,15.323) AK46(-26.435,15.323) AK48(-27.349,15.323) AK50(-28.263,15.323) AK52(-29.178,15.323) AK53(-30.092,15.323) AK55(-31.007,15.323) AK56(-31.921,15.323) AK58(-32.835,15.323) AK60(-33.75,15.323) AK62(-34.774,15.458) AK63(-35.427,15.291) AK64(-36.077,15.291) AK65(-36.727,15.291) AK66(-37.377,15.291) AK67(-38.028,15.291) AK68(-38.678,15.143) AK69(-39.653,15.143) AL2(-0.975,16.107) AL4(-1.951,16.107) AL23(-13.176,15.788) AL25(-14.09,15.788) AL27(-15.005,15.788) AL28(-15.919,15.788) AL30(-16.833,15.788) AL32(-17.748,15.788) AL33(-18.662,15.788) AL35(-19.577,15.788) AL37(-20.491,15.788) AL38(-21.405,15.788) AL40(-22.32,15.788) AL42(-23.234,15.788) AL43(-24.149,15.788) AL45(-25.063,15.788) AL46(-25.977,15.788) AL48(-26.892,15.788) AL50(-27.806,15.788) AL52(-28.721,15.788) AL53(-29.635,15.788) AL55(-30.549,15.788) AL56(-31.464,15.788) AL58(-32.378,15.788) AL60(-33.293,15.788) AL61(-34.207,15.788) AL63(-35.427,16.159) AL64(-36.077,16.159) AL65(-36.727,16.159) AL66(-37.377,16.159) AM4(-1.951,16.77) AM5(-2.66,16.261) AM7(-3.575,16.261) AM8(-4.489,16.261) AM10(-5.403,16.261) AM11(-6.318,16.261) AM13(-7.232,16.261) AM15(-8.147,16.261) AM16(-9.061,16.261) AM18(-9.975,16.261) AM20(-10.89,16.261) AM21(-11.804,16.261) AM22(-12.719,16.261) AM23(-13.633,16.261) AM25(-14.547,16.261) AM27(-15.462,16.261) AM28(-16.376,16.261) AM30(-17.291,16.261) AM32(-18.205,16.261) AM33(-19.119,16.261) AM35(-20.034,16.261) AM37(-20.948,16.261) AM38(-21.863,16.261) AM40(-22.777,16.261) AM42(-23.691,16.261) AM43(-24.606,16.261) AM45(-25.52,16.261) AM46(-26.435,16.261) AM48(-27.349,16.261) AM50(-28.263,16.261) AM52(-29.178,16.261) AM53(-30.092,16.261) AM55(-31.007,16.261) AM56(-31.921,16.261) AM58(-32.835,16.261) AM60(-33.75,16.261) AM61(-34.664,16.261) AM68(-38.353,16.37) AM69(-39.003,16.37) AN3(-1.626,17.433) AN5(-2.66,16.911) AN7(-3.575,16.911) AN8(-4.489,16.911) AN10(-5.403,16.911) AN11(-6.318,16.911) AN13(-7.232,16.911) AN15(-8.147,16.911) AN16(-9.061,16.911) AN18(-9.975,16.911) AN20(-10.89,16.911) AN21(-11.804,16.911) AN22(-12.719,16.911) AN23(-13.633,16.911) AN25(-14.547,16.911) AN27(-15.462,16.911) AN28(-16.376,16.911) AN30(-17.291,16.911) AN32(-18.205,16.911) AN33(-19.119,16.911) AN35(-20.034,16.911) AN37(-20.948,16.911) AN38(-21.863,16.911) AN40(-22.777,16.911) AN42(-23.691,16.911) AN43(-24.606,16.911) AN45(-25.52,16.911) AN46(-26.435,16.911) AN48(-27.349,16.911) AN50(-28.263,16.911) AN52(-29.178,16.911) AN53(-30.092,16.911) AN55(-31.007,16.911) AN56(-31.921,16.911) AN58(-32.835,16.911) AN60(-33.75,16.911) AN61(-34.664,16.911) AN63(-35.579,16.911) AN65(-36.493,16.911) AN66(-37.407,16.911) AN68(-38.678,17.033) AN69(-39.328,17.033) AP4(-1.951,18.096) AP5(-2.66,17.561) AP7(-3.575,17.561) AP8(-4.489,17.561) AP10(-5.403,17.561) AP11(-6.318,17.561) AP13(-7.232,17.561) AP15(-8.147,17.561) AP16(-9.061,17.561) AP18(-9.975,17.561) AP20(-10.89,17.561) AP21(-11.804,17.561) AP22(-12.719,17.561) AP23(-13.633,17.561) AP25(-14.547,17.561) AP27(-15.462,17.561) AP28(-16.376,17.561) AP30(-17.291,17.561) AP32(-18.205,17.561) AP33(-19.119,17.561) AP35(-20.034,17.561) AP37(-20.948,17.561) AP38(-21.863,17.561) AP40(-22.777,17.561) AP42(-23.691,17.561) AP43(-24.606,17.561) AP45(-25.52,17.561) AP46(-26.435,17.561) AP48(-27.349,17.561) AP50(-28.263,17.561) AP52(-29.178,17.561) AP53(-30.092,17.561) AP55(-31.007,17.561) AP56(-31.921,17.561) AP58(-32.835,17.561) AP60(-33.75,17.561) AP61(-34.664,17.561) AP63(-35.579,17.561) AP65(-36.493,17.561) AP66(-37.407,17.561) AP68(-38.353,17.646) AP70(-39.572,17.646) AR5(-2.66,18.211) AR7(-3.575,18.211) AR8(-4.489,18.211) AR10(-5.403,18.211) AR11(-6.318,18.211) AR13(-7.232,18.211) AR15(-8.147,18.211) AR16(-9.061,18.211) AR18(-9.975,18.211) AR20(-10.89,18.211) AR21(-11.804,18.211) AR22(-12.719,18.211) AR23(-13.633,18.211) AR25(-14.547,18.211) AR27(-15.462,18.211) AR28(-16.376,18.211) AR30(-17.291,18.211) AR32(-18.205,18.211) AR33(-19.119,18.211) AR35(-20.034,18.211) AR37(-20.948,18.211) AR38(-21.863,18.211) AR40(-22.777,18.211) AR42(-23.691,18.211) AR43(-24.606,18.211) AR45(-25.52,18.211) AR46(-26.435,18.211) AR48(-27.349,18.211) AR50(-28.263,18.211) AR52(-29.178,18.211) AR53(-30.092,18.211) AR55(-31.007,18.211) AR56(-31.921,18.211) AR58(-32.835,18.211) AR60(-33.75,18.211) AR61(-34.664,18.211) AR63(-35.579,18.211) AR65(-36.493,18.211) AR66(-37.407,18.211) AR68(-38.678,18.26) AR69(-39.328,18.26) AT2(-0.975,18.759) AT4(-1.951,18.759) AT5(-2.66,18.862) AT7(-3.575,18.862) AT8(-4.489,18.862) AT10(-5.403,18.862) AT11(-6.318,18.862) AT13(-7.232,18.862) AT15(-8.147,18.862) AT16(-9.061,18.862) AT18(-9.975,18.862) AT20(-10.89,18.862) AT21(-11.804,18.862) AT22(-12.719,18.862) AT23(-13.633,18.862) AT25(-14.547,18.862) AT27(-15.462,18.862) AT28(-16.376,18.862) AT30(-17.291,18.862) AT32(-18.205,18.862) AT33(-19.119,18.862) AT35(-20.034,18.862) AT37(-20.948,18.862) AT38(-21.863,18.862) AT40(-22.777,18.862) AT42(-23.691,18.862) AT43(-24.606,18.862) AT45(-25.52,18.862) AT46(-26.435,18.862) AT48(-27.349,18.862) AT50(-28.263,18.862) AT52(-29.178,18.862) AT53(-30.092,18.862) AT55(-31.007,18.862) AT56(-31.921,18.862) AT58(-32.835,18.862) AT60(-33.75,18.862) AT61(-34.664,18.862) AT63(-35.579,18.862) AT65(-36.493,18.862) AT66(-37.407,18.862) AT68(-38.353,18.823) AT69(-39.003,18.823) AU4(-1.951,19.422) AU5(-2.66,19.512) AU7(-3.575,19.512) AU8(-4.489,19.512) AU10(-5.403,19.512) AU11(-6.318,19.512) AU13(-7.232,19.512) AU15(-8.147,19.512) AU16(-9.061,19.512) AU18(-9.975,19.512) AU20(-10.89,19.512) AU21(-11.804,19.512) AU22(-12.719,19.512) AU23(-13.633,19.512) AU25(-14.547,19.512) AU27(-15.462,19.512) AU28(-16.376,19.512) AU30(-17.291,19.512) AU32(-18.205,19.512) AU33(-19.119,19.512) AU35(-20.034,19.512) AU37(-20.948,19.512) AU38(-21.863,19.512) AU40(-22.777,19.512) AU42(-23.691,19.512) AU43(-24.606,19.512) AU45(-25.52,19.512) AU46(-26.435,19.512) AU48(-27.349,19.512) AU50(-28.263,19.512) AU52(-29.178,19.512) AU53(-30.092,19.512) AU55(-31.007,19.512) AU56(-31.921,19.512) AU58(-32.835,19.512) AU60(-33.75,19.512) AU61(-34.664,19.512) AU63(-35.579,19.512) AU65(-36.493,19.512) AU66(-37.407,19.512) AV3(-1.626,20.113) AV68(-38.343,20.026) AV69(-39.328,20.215) AV70(-39.978,20.215) AW1(0,20.866) AW5(-2.534,20.226) AW6(-3.184,20.353) AW7(-3.75,20.678) AW8(-4.328,20.353) AW9(-4.898,20.678) AW10(-5.561,20.353) AW11(-6.171,20.678) AW12(-6.749,20.353) AW13(-7.319,20.678) AW14(-7.982,20.353) AW15(-8.592,20.678) AW16(-9.17,20.353) AW17(-9.74,20.678) AW18(-10.403,20.353) AW20(-11.012,20.678) AW21(-11.59,20.353) AW22(-12.16,20.678) AW23(-12.849,20.353) AW25(-13.486,20.678) AW26(-14.05,20.353) AW27(-14.713,20.678) AW28(-15.326,20.353) AW29(-15.94,20.678) AW30(-16.603,20.353) AW31(-17.167,20.678) AW32(-17.83,20.353) AW33(-18.467,20.678) AW34(-19.031,20.353) AW35(-19.694,20.678) AW36(-20.307,20.353) AW37(-20.921,20.678) AW38(-21.584,20.353) AW39(-22.148,20.678) AW41(-22.785,20.353) AW42(-23.423,20.678) AW43(-23.986,20.353) AW44(-24.649,20.678) AW45(-25.263,20.353) AW46(-25.876,20.678) AW47(-26.477,20.353) AW48(-27.041,20.678) AW49(-27.669,20.353) AW50(-28.298,20.678) AW51(-28.862,20.353) AW52(-29.463,20.678) AW53(-30.076,20.353) AW54(-30.69,20.678) AW55(-31.352,20.353) AW56(-31.916,20.678) AW57(-32.554,20.353) AW59(-33.191,20.678) AW60(-33.755,20.353) AW61(-34.418,20.678) AW62(-35.032,20.353) AW63(-35.645,20.678) AW64(-36.308,20.353) AW65(-36.872,20.678) AW66(-37.407,20.215) AW67(-38.332,20.685) AW68(-38.936,20.936) AW69(-39.581,20.85) AW70(-39.999,21.349) AW71(-40.629,20.866) AY2(-0.629,21.348) AY3(-1.286,21.342) AY4(-2.04,21.357) AY5(-2.649,21.003) AY8(-4.328,21.003) AY12(-6.749,21.003) AY16(-9.17,21.003) AY21(-11.59,21.003) AY26(-14.05,21.003) AY27(-14.713,21.328) AY29(-15.94,21.328) AY30(-16.603,21.003) AY34(-19.031,21.003) AY35(-19.694,21.328) AY37(-20.921,21.328) AY38(-21.584,21.003) AY43(-23.986,21.003) AY44(-24.649,21.328) AY46(-25.876,21.328) AY47(-26.477,21.003) AY51(-28.862,21.003) AY52(-29.463,21.328) AY54(-30.69,21.328) AY55(-31.352,21.003) AY60(-33.755,21.003) AY61(-34.418,21.328) AY63(-35.645,21.328) AY64(-36.308,21.003) AY66(-37.535,21.003) AY68(-38.85,21.581) B5(-2.266,0.65) B6(-2.847,0.975) B10(-5.325,0.975) B14(-7.803,0.975) B18(-10.281,0.975) B22(-12.759,0.975) B26(-15.237,0.975) B30(-17.715,0.975) B34(-20.194,0.975) B39(-22.672,0.975) B44(-25.15,0.975) B48(-27.628,0.975) B53(-30.106,0.975) B58(-32.584,0.975) B62(-35.062,0.975) B66(-37.54,0.975) B69(-39.349,0.63) BA3(-1.279,21.999) BA5(-2.599,21.94) BA8(-4.328,21.653) BA12(-6.749,21.653) BA16(-9.17,21.653) BA21(-11.59,21.653) BA23(-12.849,21.572) BA28(-15.326,21.572) BA32(-17.83,21.572) BA36(-20.307,21.572) BA41(-22.785,21.572) BA45(-25.263,21.572) BA49(-27.669,21.653) BA53(-30.076,21.572) BA57(-32.554,21.572) BA62(-35.032,21.572) BA68(-39.349,21.999) BB4(-1.763,22.628) BB68(-38.866,22.628) C4(-1.699,0.978) C5(-2.266,1.3) C7(-3.523,1.3) C8(-4.086,0.975) C9(-4.65,1.3) C11(-6.001,1.3) C12(-6.564,0.975) C13(-7.128,1.3) C15(-8.479,1.3) C16(-9.042,0.975) C17(-9.606,1.3) C19(-10.957,1.3) C20(-11.52,0.975) C21(-12.084,1.3) C23(-13.435,1.3) C24(-13.998,0.975) C25(-14.562,1.3) C27(-15.913,1.3) C28(-16.476,0.975) C29(-17.04,1.3) C31(-18.391,1.3) C32(-18.954,0.975) C33(-19.518,1.3) C36(-20.869,1.3) C37(-21.433,0.975) C38(-21.996,1.3) C40(-23.347,1.3) C41(-23.911,0.975) C42(-24.474,1.3) C45(-25.825,1.3) C46(-26.389,0.975) C47(-26.952,1.3) C50(-28.303,1.3) C51(-28.867,0.975) C52(-29.43,1.3) C54(-30.781,1.3) C55(-31.345,0.975) C56(-31.908,1.3) C59(-33.259,1.3) C60(-33.823,0.975) C61(-34.386,1.3) C63(-35.737,1.3) C64(-36.301,0.975) C65(-36.864,1.3) C67(-38.799,1.015) C68(-38.936,1.693) C70(-39.999,1.28) D3(-0.975,1.706) D4(-1.624,1.646) D5(-2.224,1.951) D6(-2.873,1.991) D7(-3.523,1.951) D8(-4.086,1.626) D9(-4.65,1.951) D10(-5.325,1.991) D11(-6.001,1.951) D12(-6.564,1.626) D13(-7.128,1.951) D14(-7.803,1.991) D15(-8.479,1.951) D16(-9.042,1.626) D17(-9.606,1.951) D18(-10.281,1.991) D19(-10.957,1.951) D20(-11.52,1.626) D21(-12.084,1.951) D22(-12.759,1.991) D23(-13.435,1.951) D24(-13.998,1.626) D25(-14.562,1.951) D26(-15.237,1.991) D27(-15.913,1.951) D28(-16.476,1.626) D29(-17.04,1.951) D30(-17.715,1.991) D31(-18.391,1.951) D32(-18.954,1.626) D33(-19.518,1.951) D34(-20.194,1.991) D36(-20.869,1.951) D37(-21.433,1.626) D38(-21.996,1.951) D39(-22.672,1.991) D40(-23.347,1.951) D41(-23.911,1.626) D42(-24.474,1.951) D44(-25.15,1.991) D45(-25.825,1.951) D46(-26.389,1.626) D47(-26.952,1.951) D48(-27.628,1.991) D50(-28.303,1.951) D51(-28.867,1.626) D52(-29.43,1.951) D53(-30.106,1.991) D54(-30.781,1.951) D55(-31.345,1.626) D56(-31.908,1.951) D58(-32.584,1.991) D59(-33.259,1.951) D60(-33.823,1.626) D61(-34.386,1.951) D62(-35.062,1.991) D63(-35.737,1.951) D64(-36.301,1.626) D65(-36.864,1.951) D66(-37.54,1.991) D67(-38.213,1.3) D68(-39.582,1.779) D69(-38.876,2.343) D71(-40.629,1.763) E1(0,2.274) E2(-0.65,2.274) E3(-1.3,2.274) E5(-2.66,2.723) E6(-3.575,2.723) E8(-4.489,2.723) E10(-5.403,2.723) E11(-6.318,2.723) E13(-7.232,2.723) E15(-8.147,2.723) E16(-9.061,2.723) E18(-9.975,2.723) E20(-10.89,2.723) E21(-11.804,2.723) E22(-12.719,2.723) E23(-13.633,2.723) E25(-14.547,2.723) E27(-15.462,2.723) E28(-16.376,2.723) E30(-17.291,2.723) E32(-18.205,2.723) E33(-19.119,2.723) E35(-20.034,2.723) E37(-20.948,2.723) E38(-21.863,2.723) E40(-22.777,2.723) E42(-23.691,2.723) E43(-24.606,2.723) E45(-25.52,2.723) E46(-26.435,2.723) E48(-27.349,2.723) E50(-28.263,2.723) E52(-29.178,2.723) E53(-30.092,2.723) E55(-31.007,2.723) E56(-31.921,2.723) E58(-32.835,2.723) E60(-33.75,2.723) E61(-34.664,2.723) E63(-35.629,2.659) E65(-36.645,2.659) E66(-37.661,2.659) E68(-38.213,1.951) F2(-0.975,2.848) F4(-1.951,2.848) F5(-2.66,3.373) F6(-3.575,3.373) F8(-4.489,3.373) F10(-5.403,3.373) F11(-6.318,3.373) F13(-7.232,3.373) F15(-8.147,3.373) F16(-9.061,3.373) F18(-9.975,3.373) F20(-10.89,3.373) F21(-11.804,3.373) F22(-12.719,3.373) F23(-13.633,3.373) F25(-14.547,3.373) F27(-15.462,3.373) F28(-16.376,3.373) F30(-17.291,3.373) F32(-18.205,3.373) F33(-19.119,3.373) F35(-20.034,3.373) F37(-20.948,3.373) F38(-21.863,3.373) F40(-22.777,3.373) F42(-23.691,3.373) F43(-24.606,3.373) F45(-25.52,3.373) F46(-26.435,3.373) F48(-27.349,3.373) F50(-28.263,3.373) F52(-29.178,3.373) F53(-30.092,3.373) F55(-31.007,3.373) F56(-31.921,3.373) F58(-32.835,3.373) F60(-33.75,3.373) F61(-34.664,3.373) F63(-35.629,3.31) F65(-36.645,3.31) F66(-37.661,3.31) F68(-38.876,2.994) G4(-1.951,3.511) G5(-2.66,4.023) G6(-3.575,4.023) G8(-4.489,4.023) G10(-5.403,4.023) G11(-6.318,4.023) G13(-7.232,4.023) G15(-8.147,4.023) G16(-9.061,4.023) G18(-9.975,4.023) G20(-10.89,4.023) G21(-11.804,4.023) G22(-12.719,4.023) G23(-13.633,4.023) G25(-14.547,4.023) G27(-15.462,4.023) G28(-16.376,4.023) G30(-17.291,4.023) G32(-18.205,4.023) G33(-19.119,4.023) G35(-20.034,4.023) G37(-20.948,4.023) G38(-21.863,4.023) G40(-22.777,4.023) G42(-23.691,4.023) G43(-24.606,4.023) G45(-25.52,4.023) G46(-26.435,4.023) G48(-27.349,4.023) G50(-28.263,4.023) G52(-29.178,4.023) G53(-30.092,4.023) G55(-31.007,4.023) G56(-31.921,4.023) G58(-32.835,4.023) G60(-33.75,4.023) G61(-34.664,4.023) G63(-35.629,3.96) G65(-36.645,3.96) G66(-37.661,3.96) G68(-38.678,3.655) G69(-39.328,3.655) H3(-1.626,4.174) H5(-2.66,4.674) H6(-3.575,4.674) H8(-4.489,4.674) H10(-5.403,4.674) H11(-6.318,4.674) H13(-7.232,4.674) H15(-8.147,4.674) H16(-9.061,4.674) H18(-9.975,4.674) H20(-10.89,4.674) H21(-11.804,4.674) H63(-35.629,4.61) H65(-36.645,4.61) H66(-37.661,4.61) H69(-39.003,4.218) J4(-1.951,4.837) J5(-2.66,5.324) J6(-3.575,5.324) J8(-4.489,5.324) J10(-5.403,5.324) J11(-6.318,5.324) J13(-7.232,5.324) J22(-13.176,4.488) J23(-14.09,4.488) J25(-15.005,4.488) J27(-15.919,4.488) J28(-16.833,4.488) J30(-17.748,4.488) J32(-18.662,4.488) J33(-19.577,4.488) J35(-20.491,4.488) J37(-21.405,4.488) J38(-22.32,4.488) J40(-23.234,4.488) J42(-24.149,4.488) J43(-25.063,4.488) J45(-25.977,4.488) J46(-26.892,4.488) J48(-27.806,4.488) J50(-28.721,4.488) J52(-29.635,4.488) J53(-30.549,4.488) J55(-31.464,4.488) J56(-32.378,4.488) J58(-33.293,4.488) J60(-34.207,4.488) J68(-38.676,4.794) K15(-8.126,5.438) K16(-8.776,5.438) K17(-9.426,5.438) K18(-10.077,5.438) K19(-10.727,5.438) K20(-11.377,5.438) K21(-12.027,5.438) K22(-12.719,4.952) K23(-13.633,4.952) K25(-14.547,4.952) K27(-15.462,4.952) K28(-16.376,4.952) K30(-17.291,4.952) K32(-18.205,4.952) K33(-19.119,4.952) K35(-20.034,4.952) K37(-20.948,4.952) K38(-21.863,4.952) K40(-22.777,4.952) K42(-23.691,4.952) K43(-24.606,4.952) K45(-25.52,4.952) K46(-26.435,4.952) K48(-27.349,4.952) K50(-28.263,4.952) K52(-29.178,4.952) K53(-30.092,4.952) K55(-31.007,4.952) K56(-31.921,4.952) K58(-32.835,4.952) K60(-33.75,4.952) K61(-34.664,4.952) K63(-35.447,5.26) K64(-36.097,5.26) K65(-36.747,5.26) K66(-37.398,5.26) K67(-38.048,5.26) K68(-38.666,5.468) K70(-39.653,5.57) L2(-0.975,5.5) L4(-1.951,5.5) L6(-2.729,5.974) L7(-3.379,5.974) L8(-4.029,5.974) L9(-4.679,5.974) L10(-5.33,5.974) L11(-5.98,5.974) L12(-6.63,5.974) L13(-7.28,5.974) L15(-8.126,6.276) L16(-8.776,6.276) L17(-9.426,6.276) L18(-10.077,6.276) L19(-10.727,6.276) L20(-11.377,6.276) L21(-12.027,6.276) L62(-34.958,5.689) L63(-35.427,6.147) L64(-36.077,6.147) L65(-36.727,6.147) L66(-37.377,6.147) L67(-38.028,6.147) L68(-38.678,6.147) L69(-39.328,6.147) L70(-39.978,6.147) L71(-40.629,6.147) M4(-1.951,6.163) M62(-34.958,6.604) N3(-1.626,6.826) N6(-2.729,6.914) N7(-3.379,6.914) N8(-4.029,6.914) N9(-4.679,6.914) N10(-5.33,6.914) N11(-5.98,6.914) N12(-6.63,6.914) N13(-7.28,6.914) N15(-8.126,7.114) N16(-8.776,7.114) N17(-9.426,7.114) N18(-10.077,7.114) N19(-10.727,7.114) N20(-11.377,7.114) N21(-12.027,7.114) N63(-35.427,7.061) N64(-36.077,7.061) N65(-36.727,7.061) N66(-37.377,7.061) N67(-38.028,7.061) N68(-38.678,7.061) N69(-39.328,7.061) N70(-39.978,7.061) N71(-40.629,7.061) P4(-1.951,7.489) P15(-8.126,7.952) P16(-8.776,7.952) P17(-9.426,7.952) P18(-10.077,7.952) P19(-10.727,7.952) P20(-11.377,7.952) P21(-12.027,7.952) P62(-34.958,7.518) R6(-2.729,7.981) R7(-3.379,7.981) R8(-4.029,7.981) R9(-4.679,7.981) R10(-5.33,7.981) R11(-5.98,7.981) R12(-6.63,7.981) R13(-7.28,7.981) R63(-35.427,7.975) R64(-36.077,7.975) R65(-36.727,7.975) R66(-37.377,7.975) R67(-38.028,7.975) R68(-38.678,7.975) R69(-39.328,7.975) R70(-39.978,7.975) R71(-40.629,7.975) T2(-0.975,8.152) T4(-1.951,8.152) T15(-8.126,8.791) T16(-8.776,8.791) T17(-9.426,8.791) T18(-10.077,8.791) T19(-10.727,8.791) T20(-11.377,8.791) T21(-12.027,8.791) T62(-34.958,8.433) U4(-1.951,8.815) U6(-2.729,9.047) U7(-3.379,9.047) U8(-4.029,9.047) U9(-4.679,9.047) U10(-5.33,9.047) U11(-5.98,9.047) U12(-6.63,9.047) U13(-7.28,9.047) U63(-35.427,8.89) U64(-36.077,8.89) U65(-36.727,8.89) U66(-37.377,8.89) U67(-38.028,8.89) U68(-38.678,8.89) U69(-39.328,8.89) U70(-39.978,8.89) U71(-40.629,8.89) V3(-1.626,9.478) V15(-8.126,9.629) V16(-8.776,9.629) V17(-9.426,9.629) V18(-10.077,9.629) V19(-10.727,9.629) V20(-11.377,9.629) V21(-12.027,9.629) V62(-34.958,9.347) W4(-1.951,10.141) W6(-2.729,10.114) W7(-3.379,10.114) W8(-4.029,10.114) W9(-4.679,10.114) W10(-5.33,10.114) W11(-5.98,10.114) W12(-6.63,10.114) W13(-7.28,10.114) W63(-35.427,9.804) W64(-36.077,9.804) W65(-36.727,9.804) W66(-37.377,9.804) W67(-38.028,9.804) W68(-38.678,9.804) W69(-39.328,9.804) W70(-39.978,9.804) W71(-40.629,9.804) Y15(-8.126,10.467) Y16(-8.776,10.467) Y17(-9.426,10.467) Y18(-10.077,10.467) Y19(-10.727,10.467) Y20(-11.377,10.467) Y21(-12.027,10.467) Y62(-34.958,10.261)
  oval 0.254x0.343 smd: A6(-2.847,0.325) A7(-3.523,0) A9(-4.65,0) A10(-5.325,0.325) A11(-6.001,0) A13(-7.128,0) A14(-7.803,0.325) A15(-8.479,0) A17(-9.606,0) A18(-10.281,0.325) A19(-10.957,0) A21(-12.084,0) A22(-12.759,0.325) A23(-13.435,0) A25(-14.562,0) A26(-15.237,0.325) A27(-15.913,0) A29(-17.04,0) A30(-17.715,0.325) A31(-18.391,0) A33(-19.518,0) A34(-20.194,0.325) A36(-20.869,0) A38(-21.996,0) A39(-22.672,0.325) A40(-23.347,0) A42(-24.474,0) A44(-25.15,0.325) A45(-25.825,0) A47(-26.952,0) A48(-27.628,0.325) A50(-28.303,0) A52(-29.43,0) A53(-30.106,0.325) A54(-30.781,0) A56(-31.908,0) A58(-32.584,0.325) A59(-33.259,0) A61(-34.386,0) A62(-35.062,0.325) A63(-35.737,0) A65(-36.864,0) A66(-37.54,0.325) A67(-38.215,0) AY7(-3.763,21.328) AY9(-4.898,21.328) AY11(-6.184,21.328) AY13(-7.319,21.328) AY15(-8.604,21.328) AY17(-9.74,21.328) AY20(-11.025,21.328) AY22(-12.16,21.328) AY25(-13.486,21.328) AY31(-17.167,21.328) AY33(-18.467,21.328) AY39(-22.148,21.328) AY42(-23.423,21.328) AY48(-27.103,21.328) AY50(-28.236,21.328) AY56(-31.916,21.328) AY59(-33.191,21.328) AY65(-36.872,21.328) AY67(-38.216,21.328) B7(-3.523,0.65) B9(-4.65,0.65) B11(-6.001,0.65) B13(-7.128,0.65) B15(-8.479,0.65) B17(-9.606,0.65) B19(-10.957,0.65) B21(-12.084,0.65) B23(-13.435,0.65) B25(-14.562,0.65) B27(-15.913,0.65) B29(-17.04,0.65) B31(-18.391,0.65) B33(-19.518,0.65) B36(-20.869,0.65) B38(-21.996,0.65) B40(-23.347,0.65) B42(-24.474,0.65) B45(-25.825,0.65) B47(-26.952,0.65) B50(-28.303,0.65) B52(-29.43,0.65) B54(-30.781,0.65) B56(-31.908,0.65) B59(-33.259,0.65) B61(-34.386,0.65) B63(-35.737,0.65) B65(-36.864,0.65) B67(-38.215,0.65) BA4(-1.948,22.004) BA6(-3.141,21.572) BA7(-3.705,21.978) BA9(-4.898,21.978) BA10(-5.561,21.572) BA11(-6.125,21.978) BA13(-7.319,21.978) BA14(-7.982,21.572) BA15(-8.546,21.978) BA17(-9.74,21.978) BA18(-10.403,21.572) BA20(-10.966,21.978) BA22(-12.16,21.978) BA25(-13.486,21.978) BA26(-14.149,21.653) BA27(-14.812,21.978) BA29(-15.841,21.978) BA30(-16.504,21.653) BA31(-17.167,21.978) BA33(-18.467,21.978) BA34(-19.13,21.653) BA35(-19.793,21.978) BA37(-20.822,21.978) BA38(-21.485,21.653) BA39(-22.148,21.978) BA42(-23.423,21.978) BA43(-24.086,21.653) BA44(-24.748,21.978) BA46(-25.777,21.978) BA47(-26.44,21.653) BA48(-27.103,21.978) BA50(-28.236,21.978) BA51(-28.899,21.653) BA52(-29.562,21.978) BA54(-30.59,21.978) BA55(-31.253,21.653) BA56(-31.916,21.978) BA59(-33.191,21.978) BA60(-33.854,21.653) BA61(-34.517,21.978) BA63(-35.546,21.978) BA64(-36.209,21.653) BA65(-36.872,21.978) BA66(-37.535,21.653) BA67(-38.216,21.978) BB5(-2.529,22.628) BB6(-3.141,22.303) BB7(-3.705,22.628) BB9(-4.898,22.628) BB10(-5.561,22.303) BB11(-6.125,22.628) BB13(-7.319,22.628) BB14(-7.982,22.303) BB15(-8.546,22.628) BB17(-9.74,22.628) BB18(-10.403,22.303) BB20(-10.966,22.628) BB22(-12.16,22.628) BB23(-12.849,22.222) BB25(-13.486,22.628) BB26(-14.149,22.303) BB27(-14.812,22.628) BB29(-15.841,22.628) BB30(-16.504,22.303) BB31(-17.167,22.628) BB32(-17.83,22.222) BB33(-18.467,22.628) BB34(-19.13,22.303) BB35(-19.793,22.628) BB37(-20.822,22.628) BB38(-21.485,22.303) BB39(-22.148,22.628) BB41(-22.785,22.222) BB42(-23.423,22.628) BB43(-24.086,22.303) BB44(-24.748,22.628) BB46(-25.777,22.628) BB47(-26.44,22.303) BB48(-27.103,22.628) BB50(-28.236,22.628) BB51(-28.899,22.303) BB52(-29.562,22.628) BB54(-30.59,22.628) BB55(-31.253,22.303) BB56(-31.916,22.628) BB57(-32.554,22.222) BB59(-33.191,22.628) BB60(-33.854,22.303) BB61(-34.517,22.628) BB63(-35.546,22.628) BB64(-36.209,22.303) BB65(-36.872,22.628) BB66(-37.535,22.303) BB67(-38.216,22.628)
  oval 0.343x0.254 smd: AA1(-0.325,10.804) AB1(0,11.467) AB2(-0.65,11.467) AB3(-1.3,11.467) AC1(-0.325,12.13) AC2(-0.975,12.13) AD1(0,12.792) AD2(-0.65,12.792) AD3(-1.3,12.792) AF1(-0.325,13.455) AF70(-39.978,13.154) AF71(-40.629,13.154) AG1(0,14.118) AG2(-0.65,14.118) AG3(-1.3,14.118) AG70(-39.653,13.817) AG71(-40.303,13.817) AH1(-0.325,14.781) AH2(-0.975,14.781) AH68(-38.678,14.48) AH69(-39.328,14.48) AH70(-39.978,14.48) AH71(-40.629,14.48) AJ1(0,15.444) AJ2(-0.65,15.444) AJ3(-1.3,15.444) AK70(-40.303,15.143) AL1(-0.325,16.107) AL68(-38.678,15.806) AL69(-39.328,15.806) AL70(-39.978,15.806) AL71(-40.629,15.806) AM1(0,16.77) AM2(-0.65,16.77) AM3(-1.3,16.77) AM70(-39.653,16.469) AM71(-40.303,16.469) AN1(-0.325,17.433) AN2(-0.975,17.433) AN70(-39.978,17.132) AN71(-40.629,17.132) AP1(0,18.096) AP2(-0.65,18.096) AP3(-1.3,18.096) AR70(-39.978,18.16) AR71(-40.629,18.16) AT1(-0.325,18.759) AT70(-39.653,18.823) AT71(-40.303,18.823) AU1(0,19.422) AU2(-0.65,19.422) AU3(-1.3,19.422) AU68(-38.678,19.461) AU69(-39.328,19.486) AU70(-39.978,19.486) AU71(-40.629,19.486) AV1(0,20.142) AV2(-0.95,20.113) AV71(-40.629,20.215) AW2(-0.625,20.677) AW3(-1.275,20.677) E70(-39.978,2.305) E71(-40.629,2.413) F1(-0.325,2.848) F70(-39.526,2.994) F71(-40.176,2.931) G1(0,3.511) G2(-0.65,3.511) G3(-1.3,3.511) G70(-39.978,3.555) G71(-40.629,3.555) H1(-0.325,4.174) H2(-0.975,4.174) H70(-39.653,4.218) H71(-40.303,4.218) J1(0,4.837) J2(-0.65,4.837) J3(-1.3,4.837) J69(-39.328,4.881) J70(-39.978,4.881) J71(-40.629,4.881) K71(-40.303,5.57) L1(-0.325,5.5) M1(0,6.163) M2(-0.65,6.163) M3(-1.3,6.163) N1(-0.325,6.826) N2(-0.975,6.826) P1(0,7.489) P2(-0.65,7.489) P3(-1.3,7.489) T1(-0.325,8.152) U1(0,8.815) U2(-0.65,8.815) U3(-1.3,8.815) V1(-0.325,9.478) V2(-0.975,9.478) W1(0,10.141) W2(-0.65,10.141) W3(-1.3,10.141)
